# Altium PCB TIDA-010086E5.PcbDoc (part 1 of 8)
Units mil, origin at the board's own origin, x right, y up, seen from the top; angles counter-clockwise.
Board outline 6400 x 6200 mil, 6 copper layers (Top Layer, Power, AGND, Signal, PGND, Bottom Layer), stack 70.536 mil thick; 717 components, 376 nets, 2259 pads, 2183 vias.
Unrouted connection lines stored in the file: 1424.
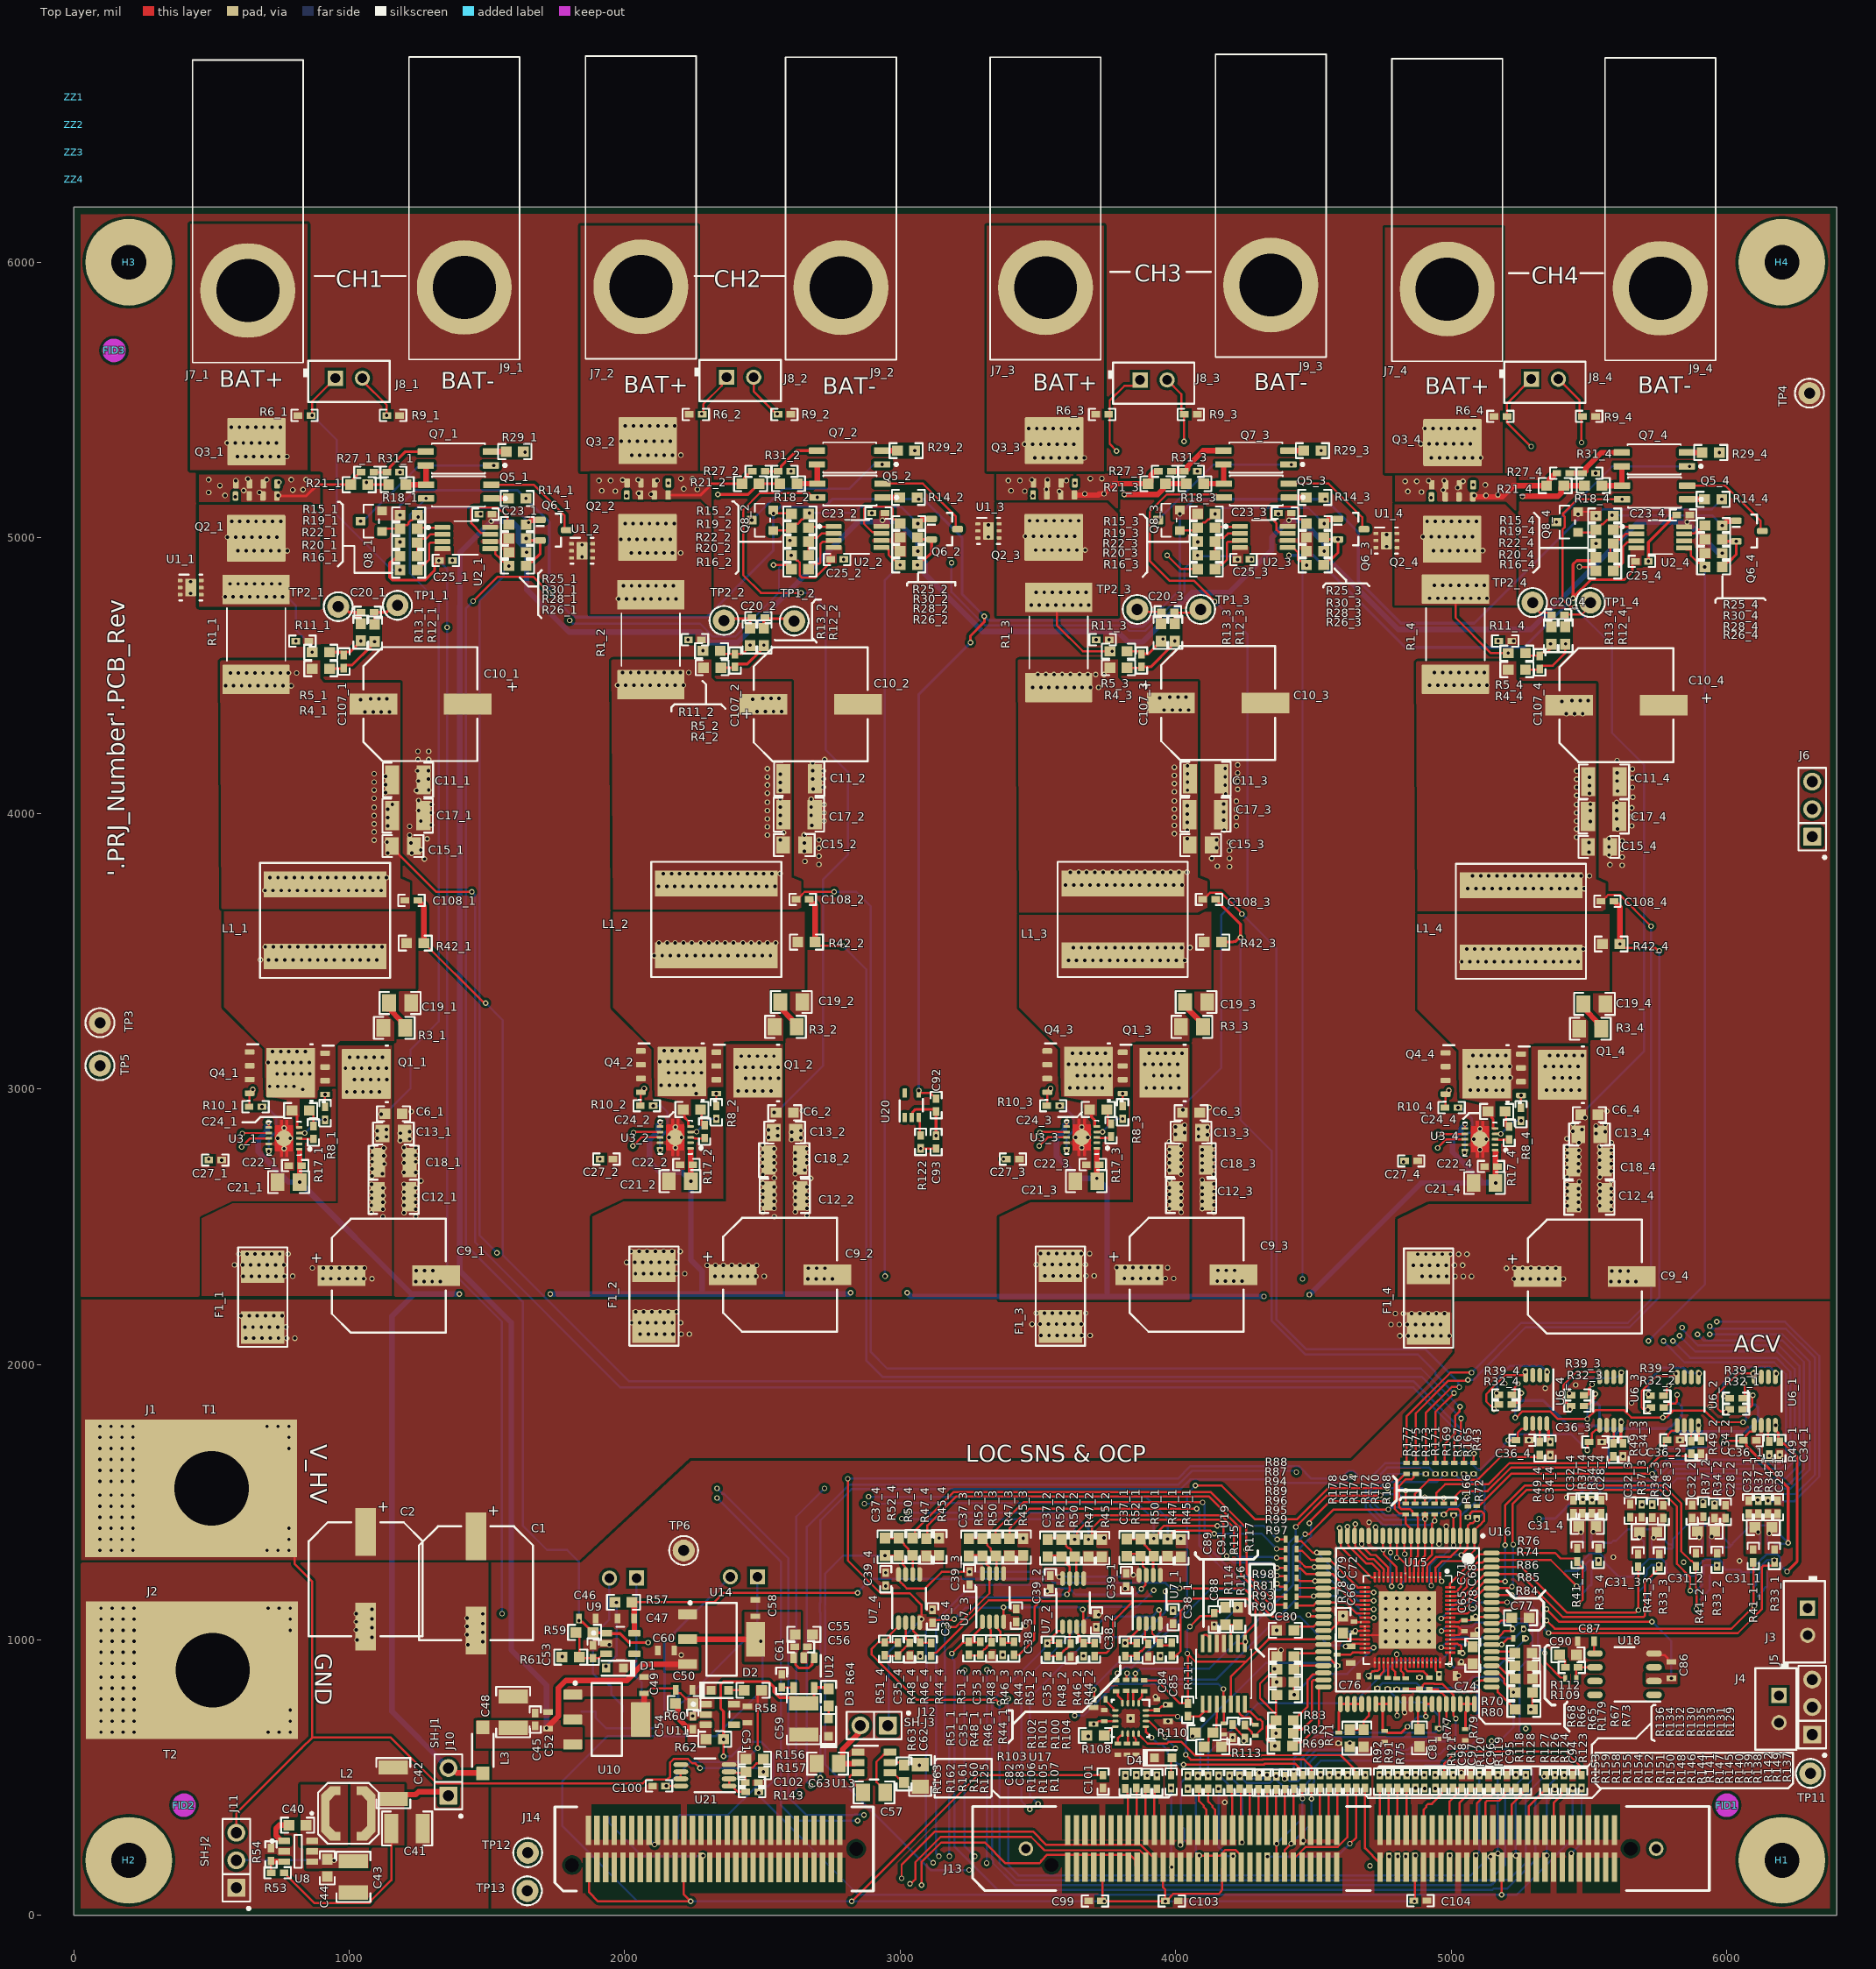
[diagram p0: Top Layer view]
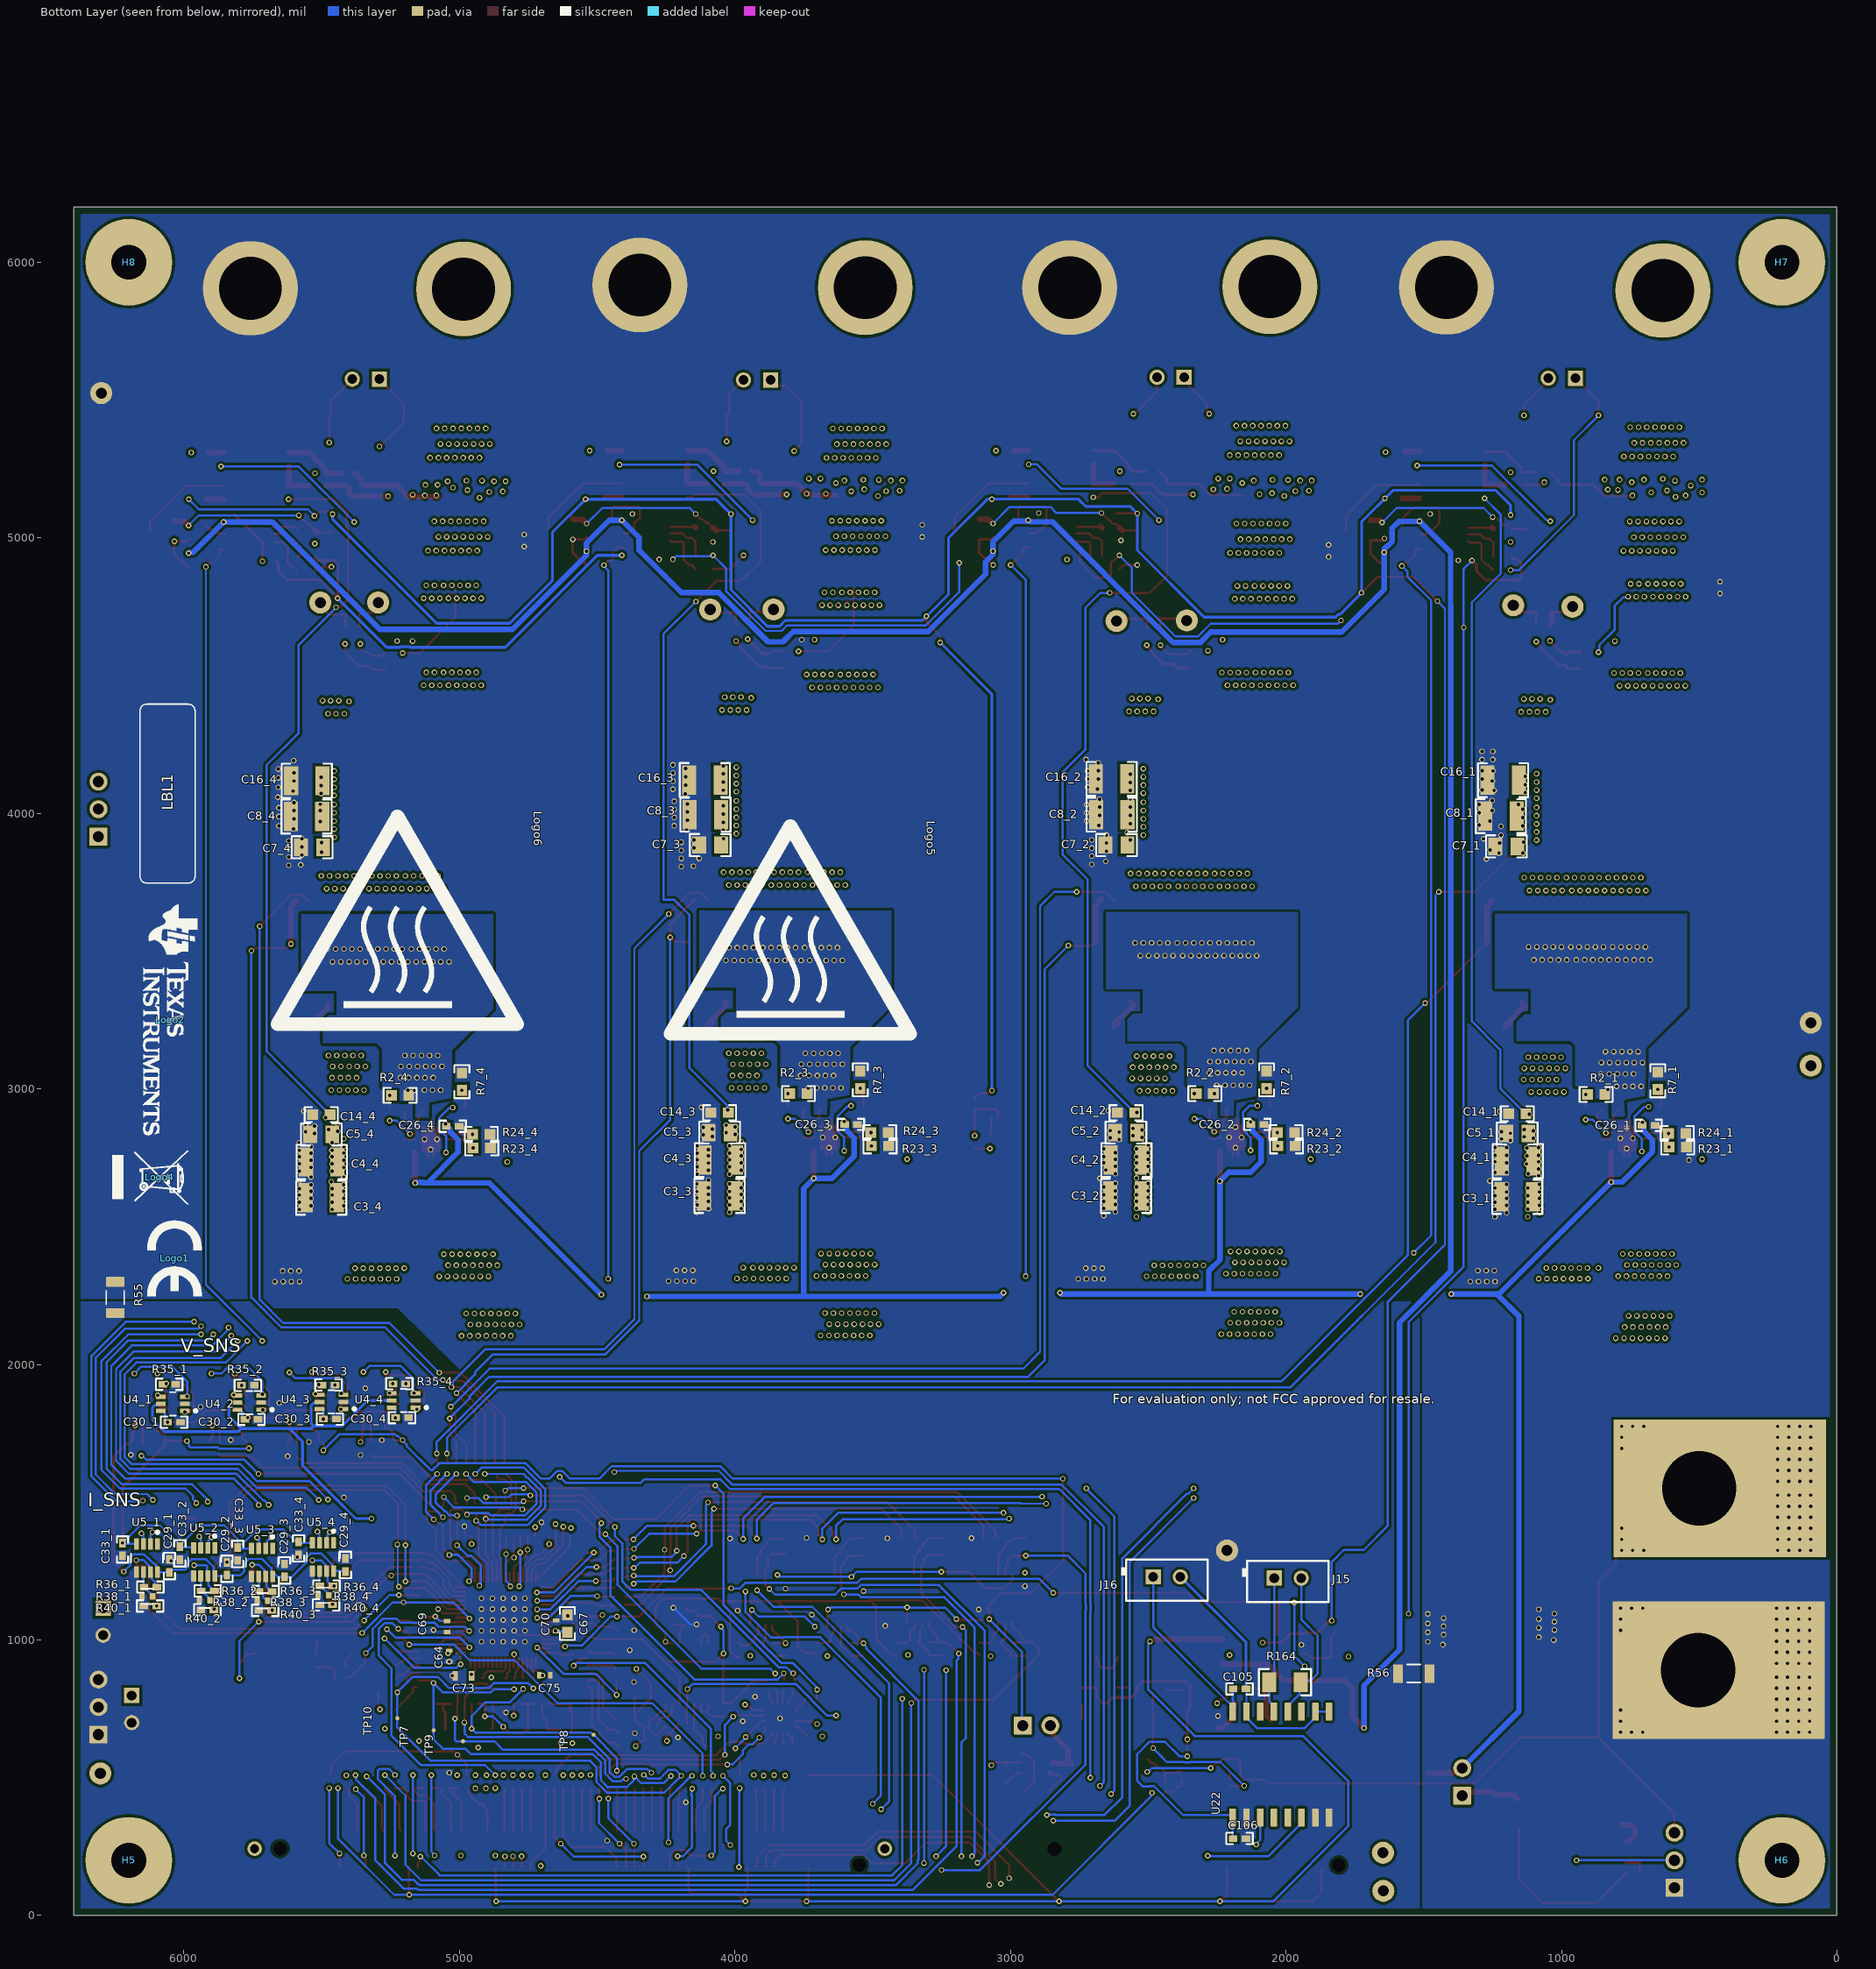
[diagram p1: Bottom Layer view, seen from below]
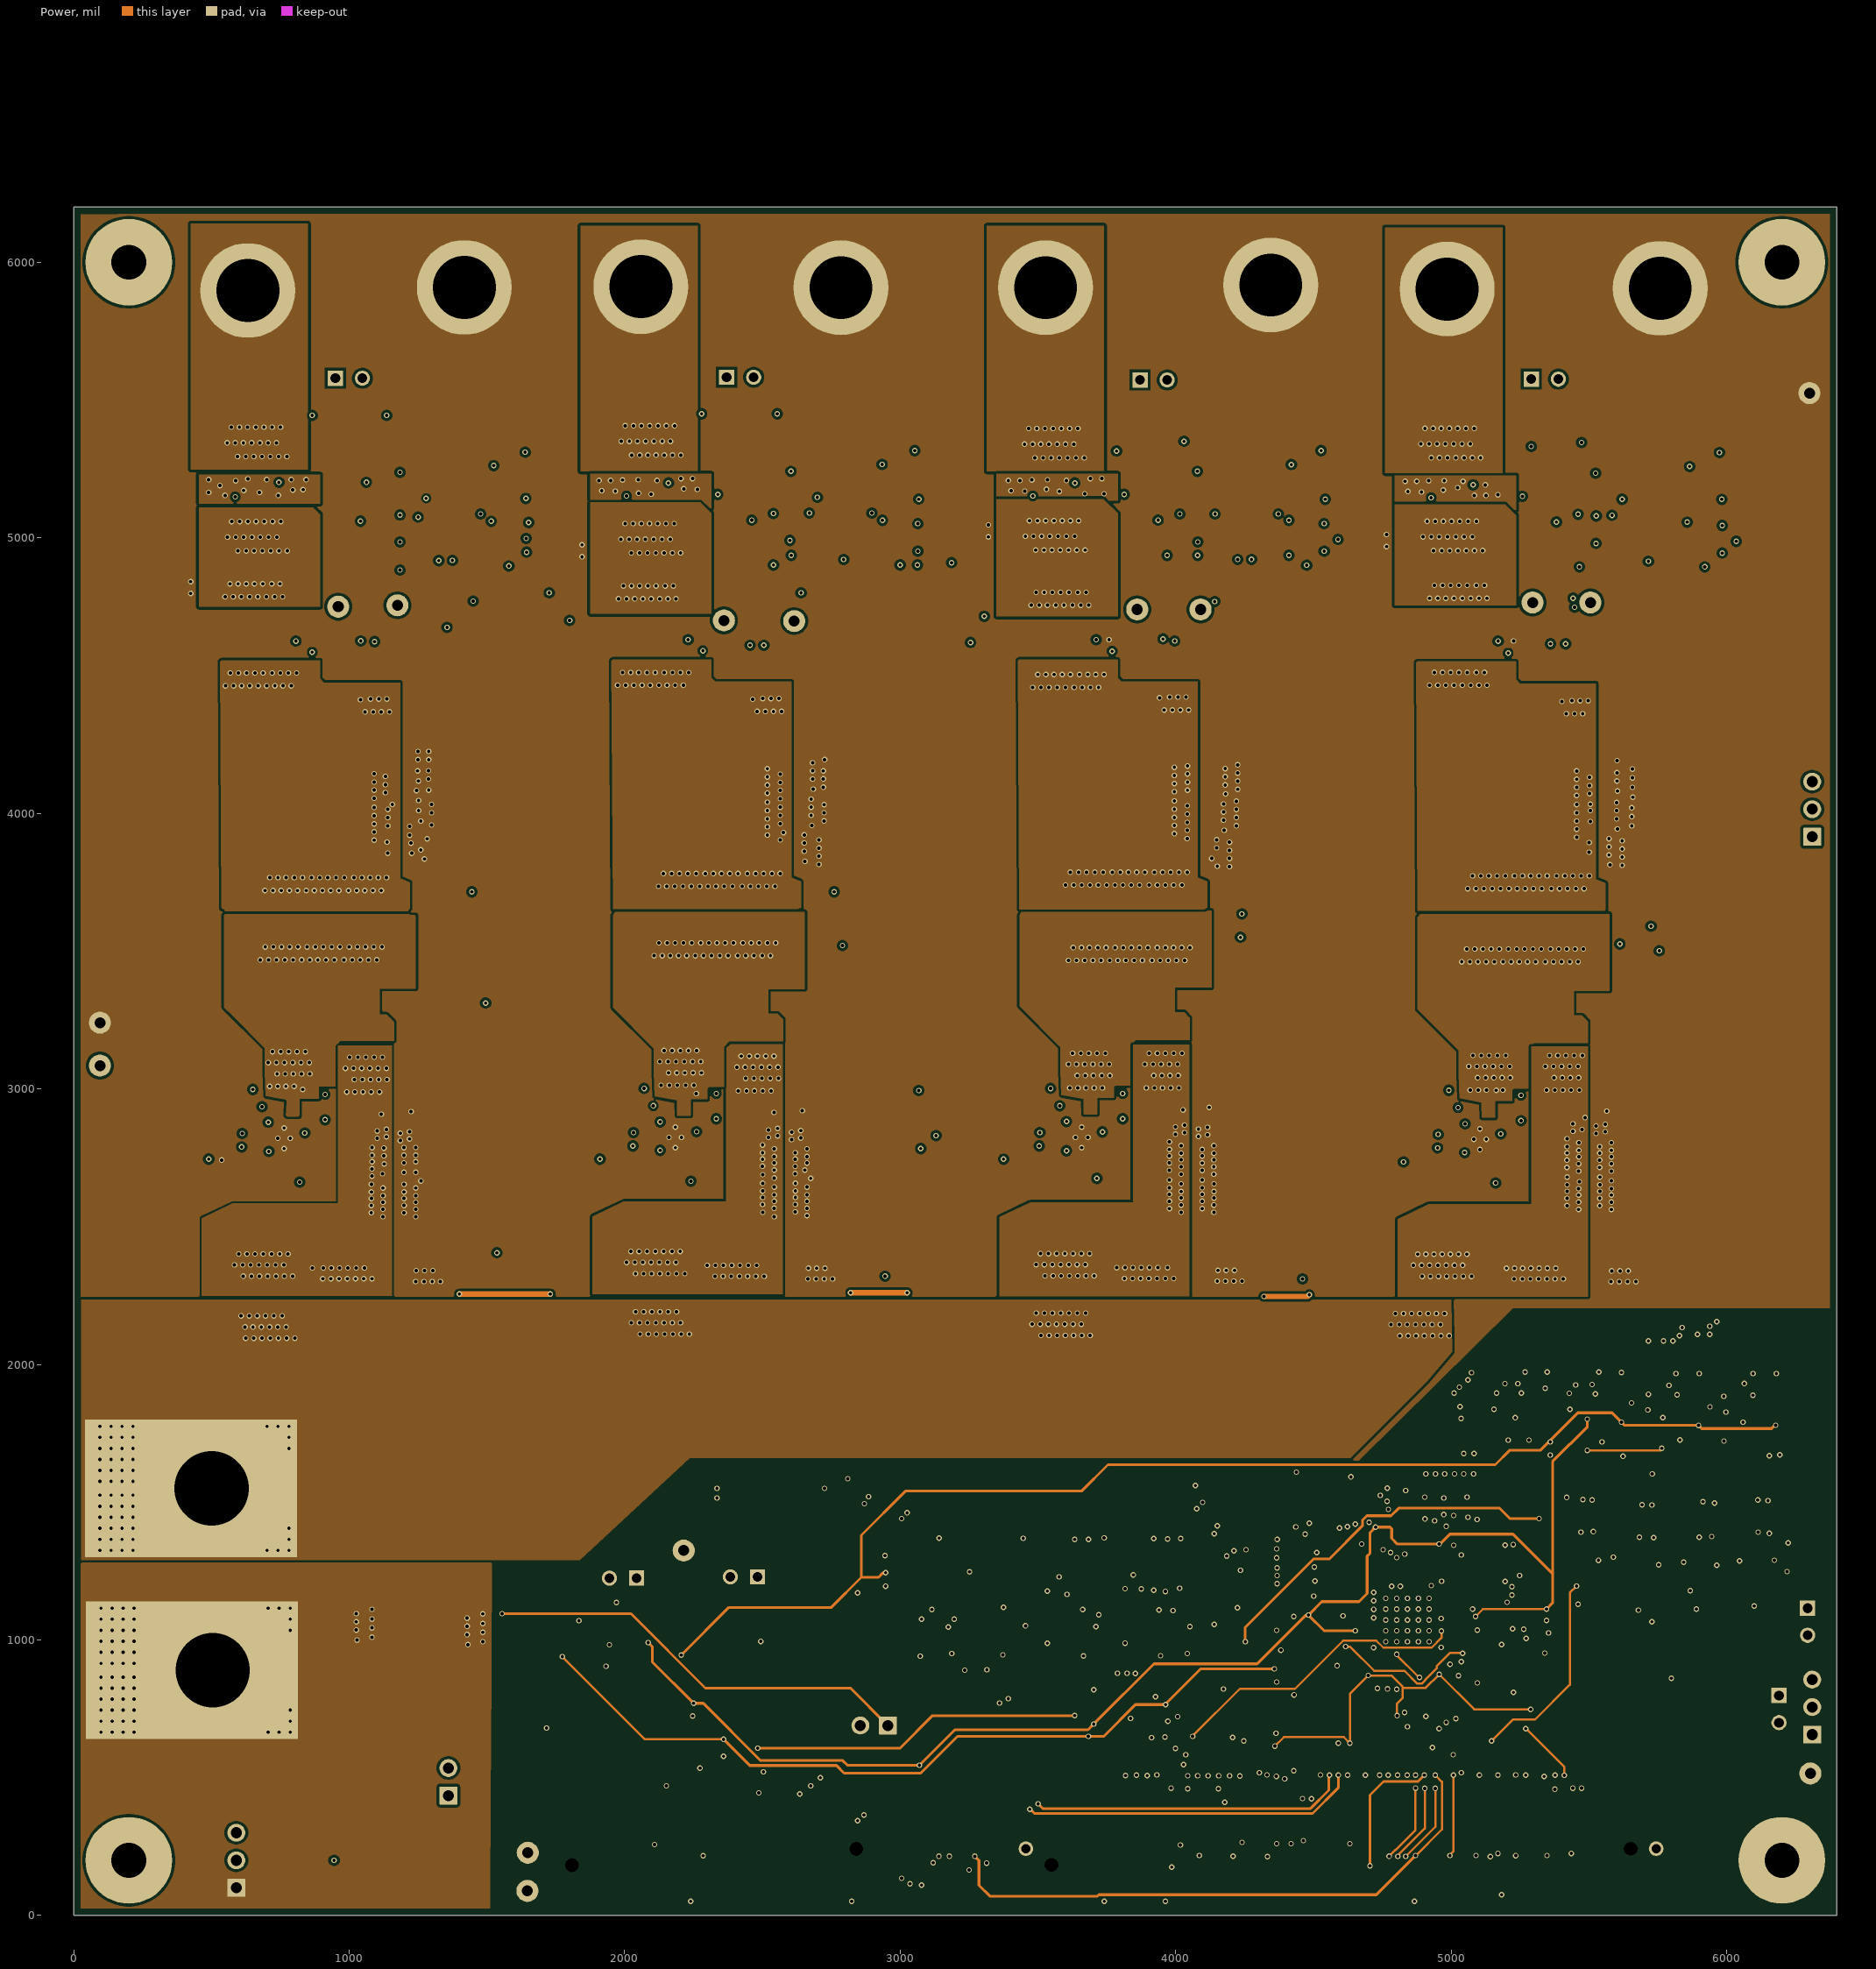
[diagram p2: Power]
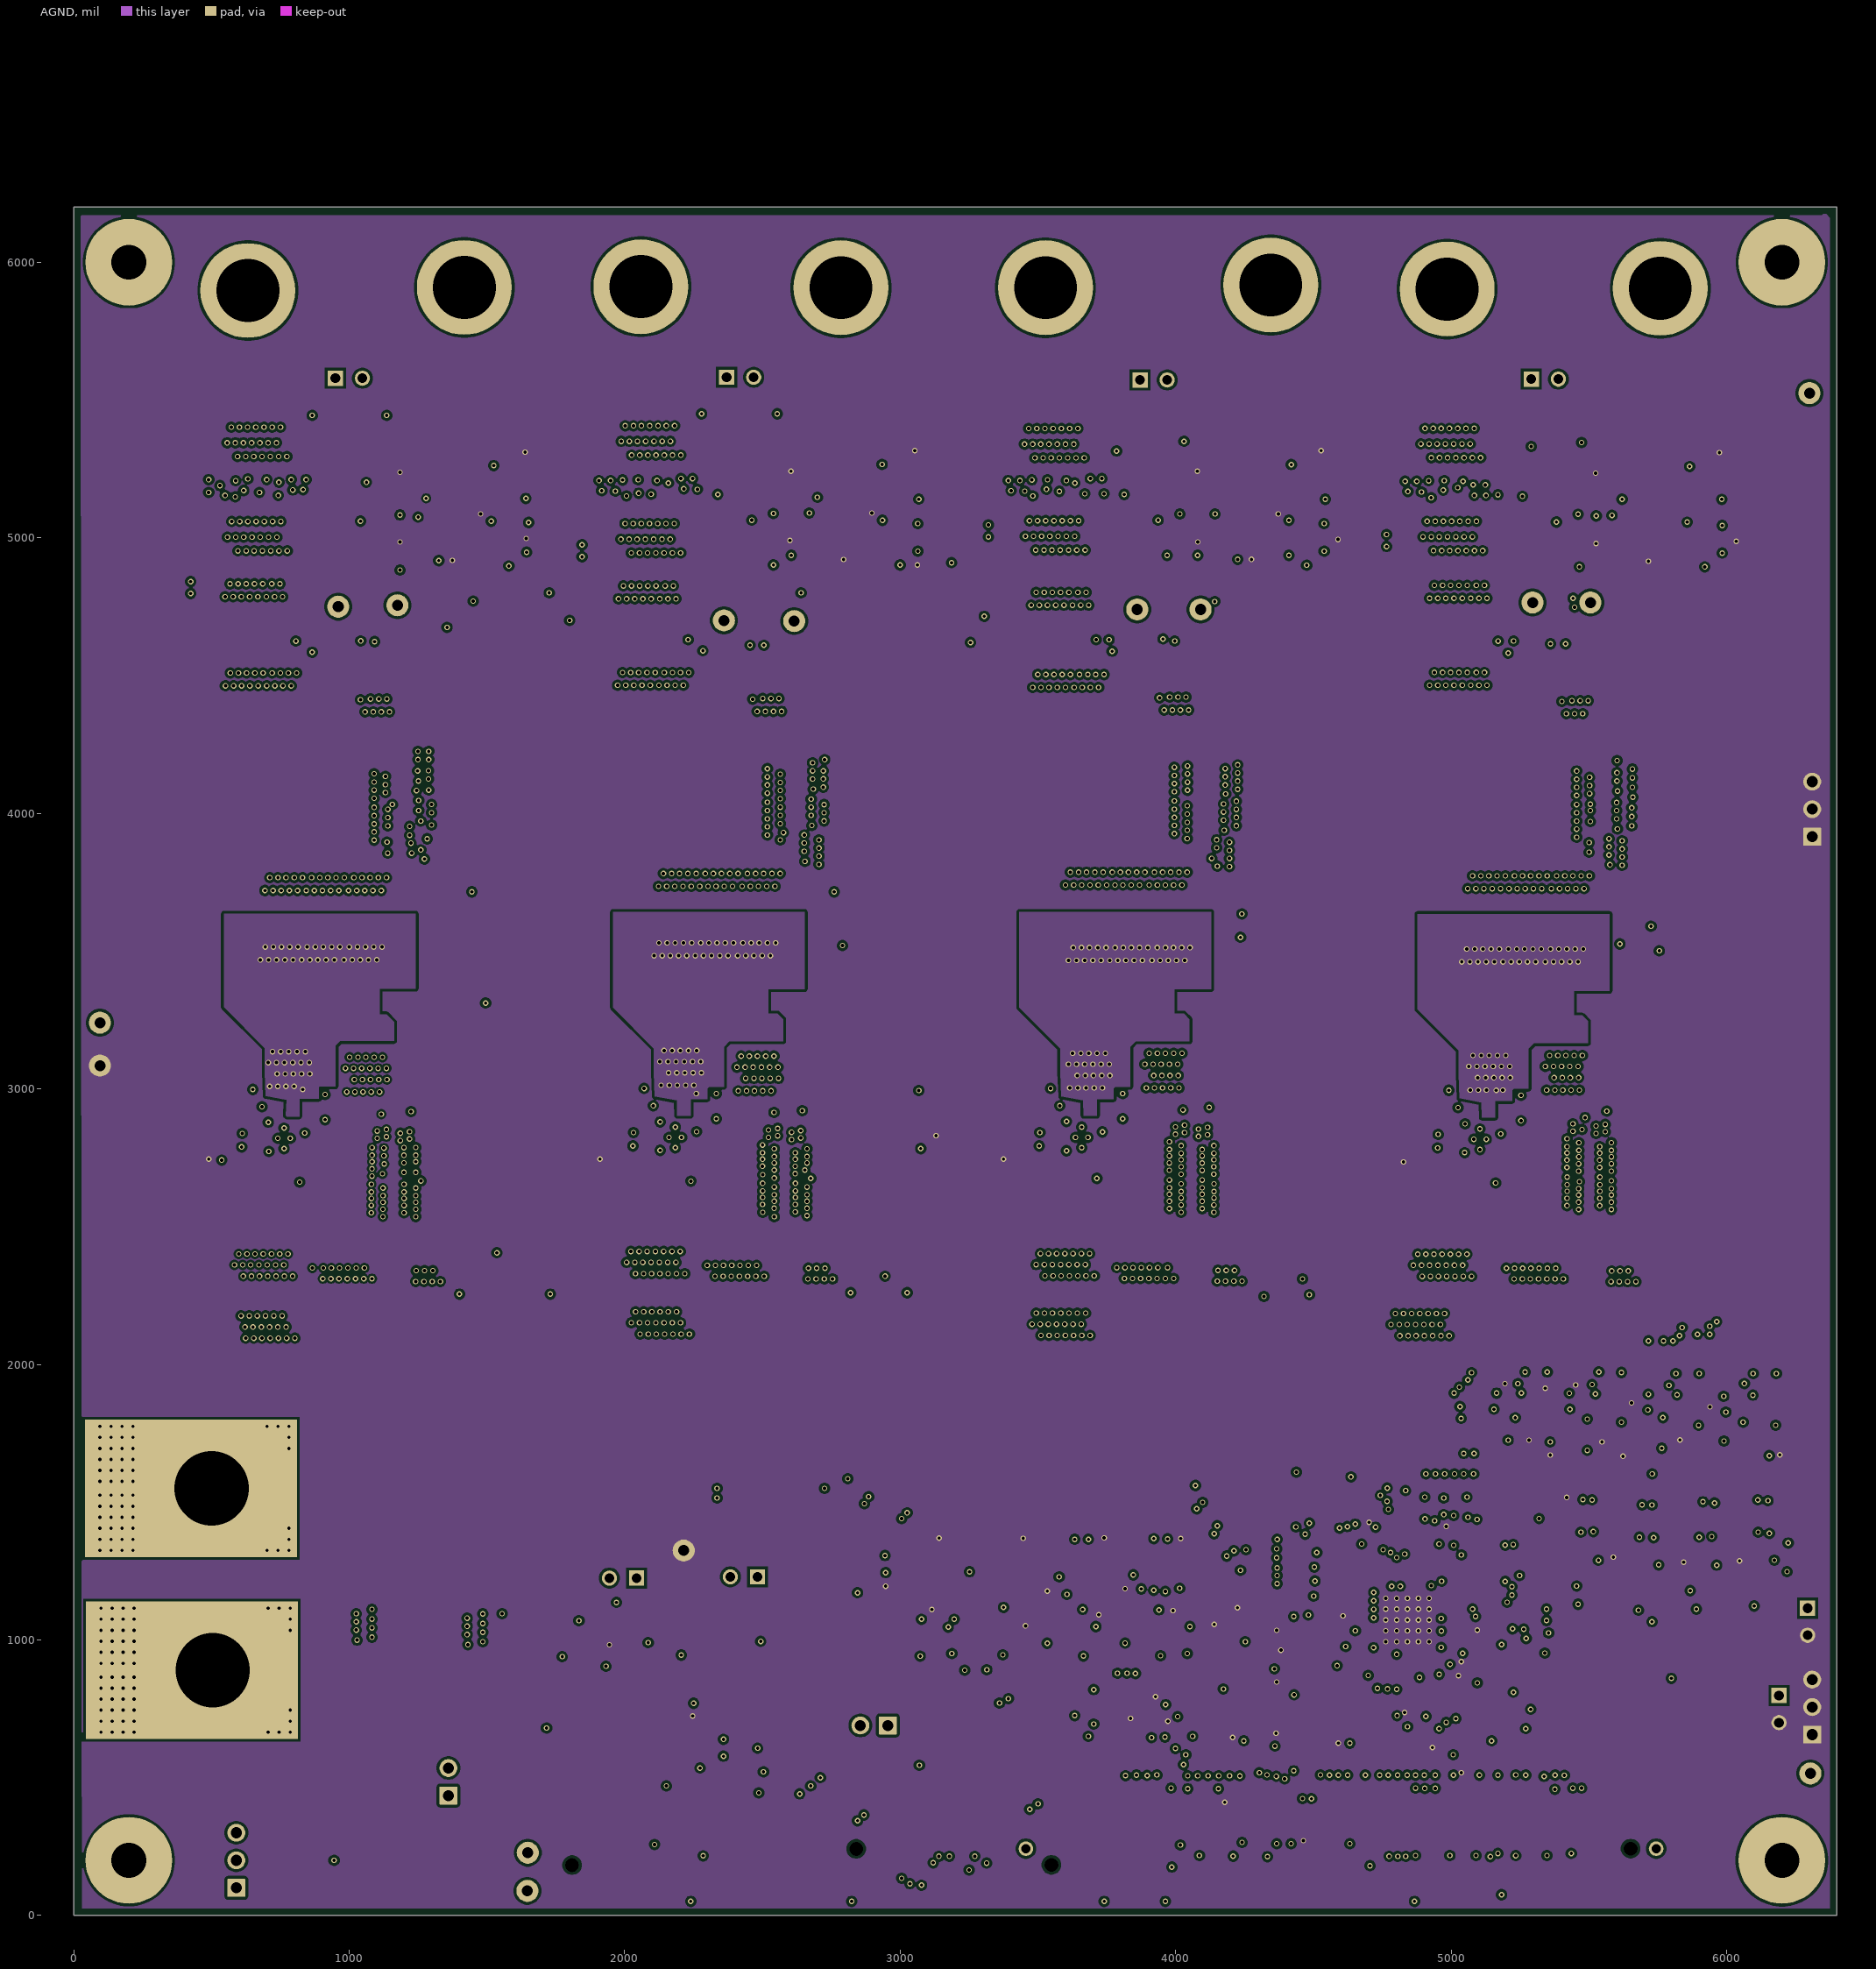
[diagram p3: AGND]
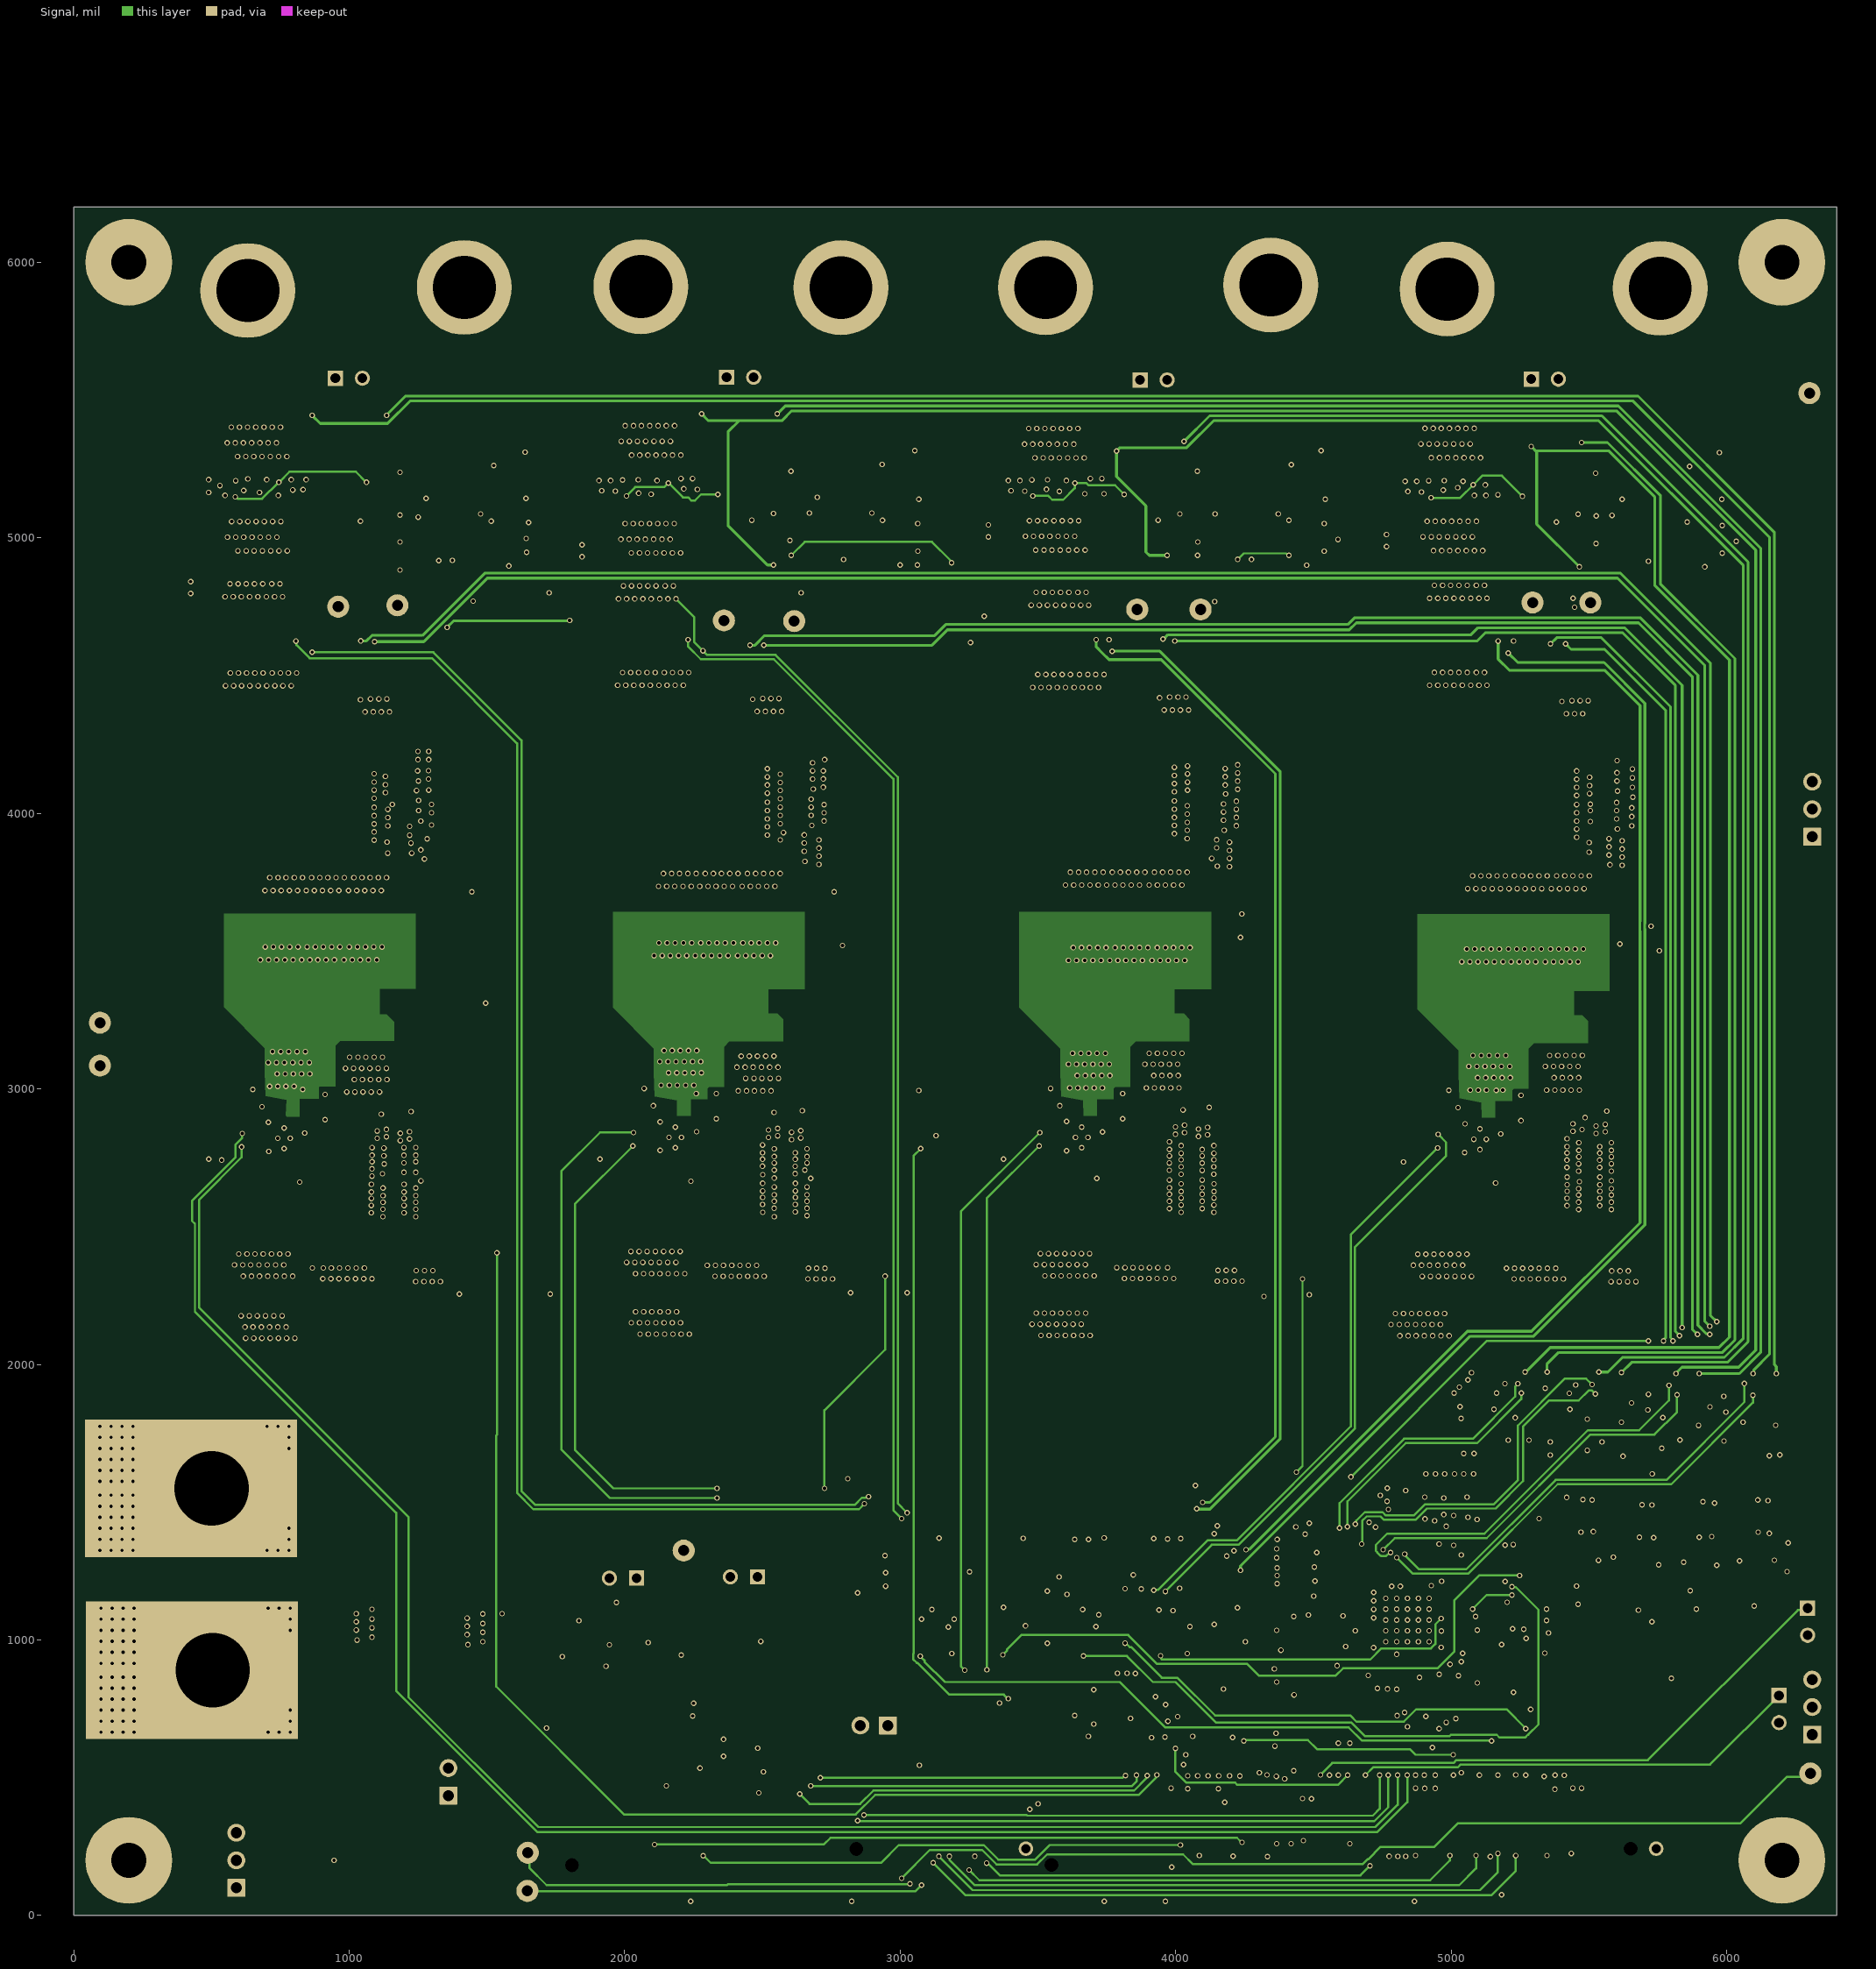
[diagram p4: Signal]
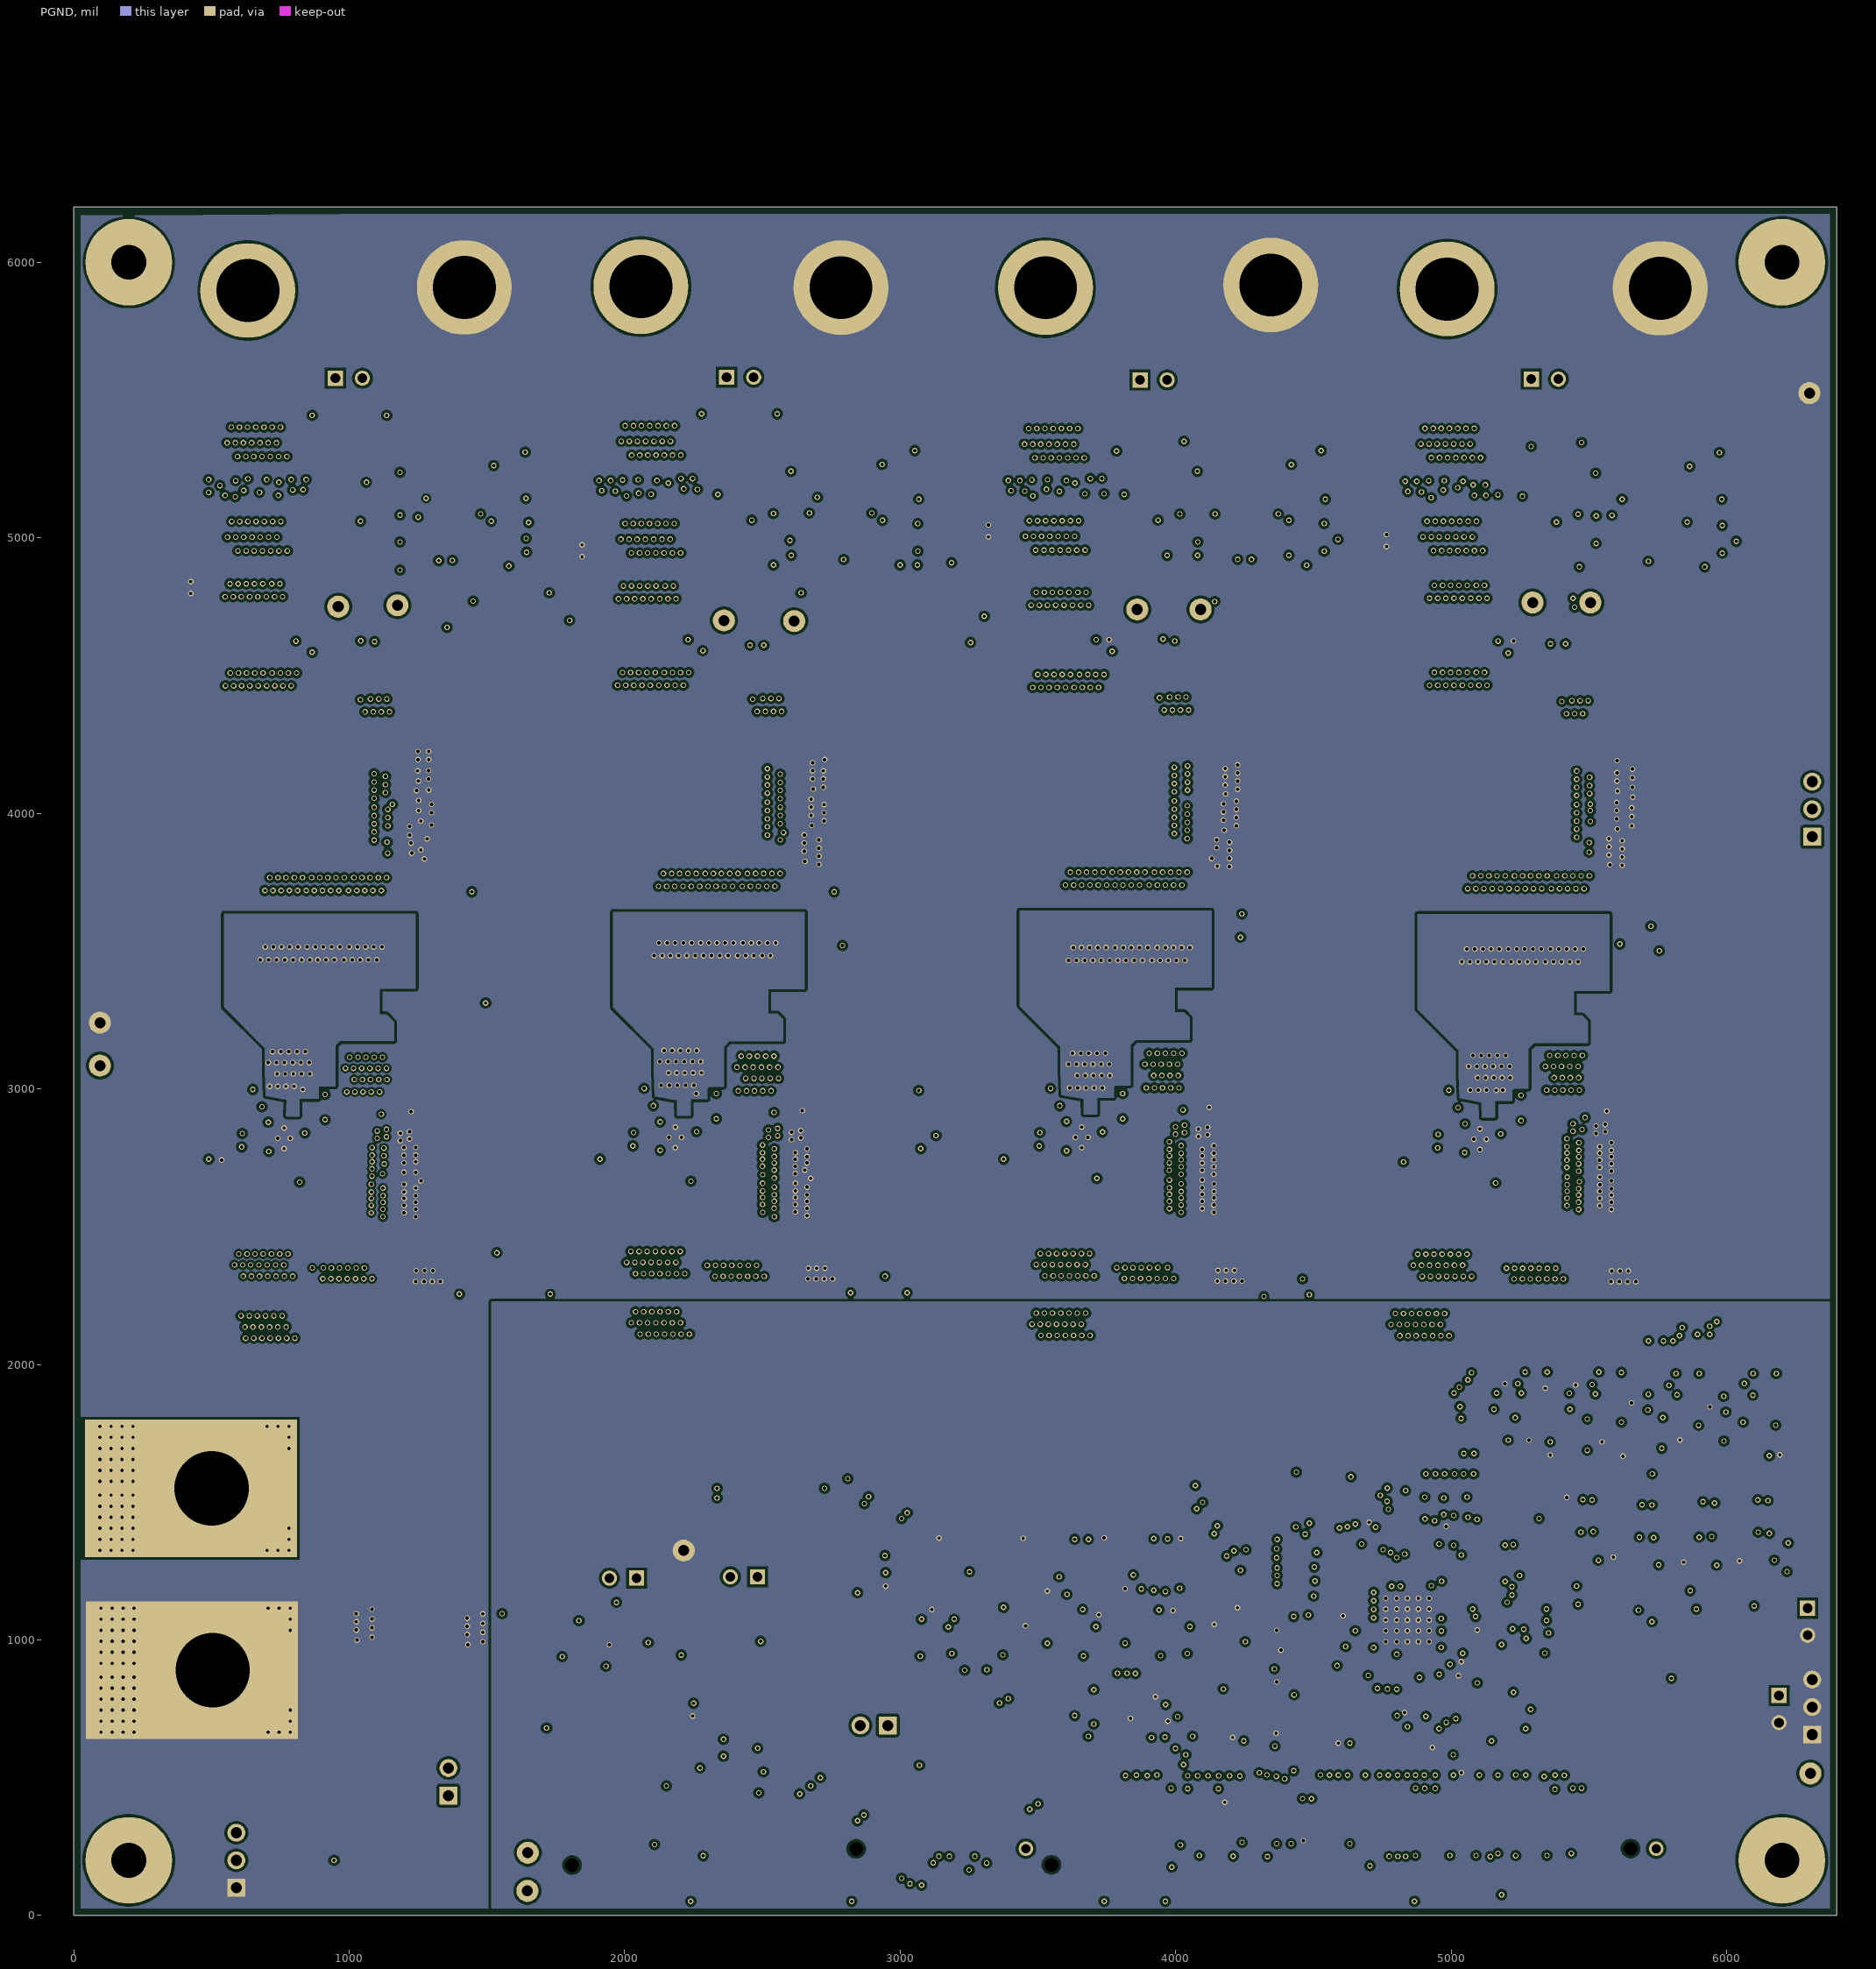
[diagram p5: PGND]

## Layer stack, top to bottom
Top Solder: solder mask 1, SM-001, Dk 4
Top Layer: signal copper 2.756
Dielectric 6: prepreg 2.8, PP-006, Dk 4.1
Dielectric 1: prepreg 5.1, PP-017, Dk 4.3
Power: signal copper 2.7559
Dielectric 4: prepreg 5.1, PP-017, Dk 4.3
AGND: signal copper 2.756
Dielectric 2: core 28, Core-039, Dk 4.8
Signal: signal copper 2.756
Dielectric 5: prepreg 5.1, PP-017, Dk 4.3
PGND: signal copper 2.7559
Dielectric 3: prepreg 5.1, PP-017, Dk 4.3
Dielectric 7: prepreg 2.8, PP-006, Dk 4.1
Bottom Layer: signal copper 2.756
Bottom Solder: solder mask 1, SM-001, Dk 4

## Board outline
0,0 6400,0 6400,6200 0,6200

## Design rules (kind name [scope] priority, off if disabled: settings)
AcuteAngle [All] p1: minimum=4.50000000000000E+0001 checktracksonly=FALSE
AssemblyTestPointUsage [All] p1: valid=2
BoardOutlineClearance BoardOutlineClearance_MountingHoles [OnCopper and InComponentClass('Mounting Holes')] p1: gap=39.37 ignorepadtopadclearanceinfootprint=FALSE
BoardOutlineClearance BoardOutlineClearance_Poly [OnCopper and IsPoly] p2: gap=25 ignorepadtopadclearanceinfootprint=FALSE
BoardOutlineClearance [OnCopper and Not InComponentClass('Logo') and not InComponentClass('FiducialMark') and not InRegion(1000,500,4000,800) and not InPoly] p3: gap=40 ignorepadtopadclearanceinfootprint=FALSE
Clearance Clearance_1 [InNet('VIN_1')] p1: gap=7.87 ignorepadtopadclearanceinfootprint=TRUE except(0: Arc-Hole Track-Hole SMDPad-Hole THPad-Hole Via-Hole Fill-Hole Poly-Hole Region-Hole Text-Hole)
Clearance Clearance_Keepouts [((IsTrack Or IsArc) And Not InPoly) And IsFree and IsKeepOut vs ((IsTrack Or IsArc) And Not InPoly) And IsFree and IsKeepOut] p2: gap=0 ignorepadtopadclearanceinfootprint=FALSE
Clearance Clearance_Poly [InPolygon] p3: gap=10 ignorepadtopadclearanceinfootprint=TRUE
Clearance Clearance_FiducialMark [IsKeepOut and InComponentClass('FiducialMark') vs IsPad and InComponentClass('FiducialMark')] p4: gap=0 ignorepadtopadclearanceinfootprint=FALSE
Clearance [All] p5: gap=7.87 ignorepadtopadclearanceinfootprint=TRUE
ComponentClearance "ADC resistors" [InComponentClass('U_TIDA-010086E5_ADC')] p1: gap=0 collisioncheckmode=3 verticalgap=0 showdistances=FALSE
ComponentClearance screw [InComponentClass('TIDA-010086E5_TopLevel')] p2: gap=0 collisioncheckmode=3 verticalgap=0 showdistances=FALSE
ComponentClearance ComponentClearance_ADC [InComponent('U16') vs InComponent('U15')] p3: gap=0 collisioncheckmode=3 verticalgap=0 showdistances=FALSE // For ADC overlaping
ComponentClearance ComponentClearance_MountingHoles_FiducialMarks [InComponentClass('Mounting Holes') vs InComponentClass('FiducialMark')] p4: gap=50 collisioncheckmode=3 verticalgap=10 showdistances=FALSE
ComponentClearance ComponentClearance_Shunt [InComponentClass('Header') vs InComponentClass('Shunt')] p5: gap=0 collisioncheckmode=3 verticalgap=0 showdistances=FALSE
ComponentClearance ComponentClearance_Logo [InComponentClass('Logo')] p6: gap=30 collisioncheckmode=3 verticalgap=10 showdistances=FALSE
ComponentClearance ComponentClearance_ScrewToNut [(HasFootprint('NY PMS 440 0025 PH')) vs (HasFootprint('Keystone_1902C'))] p7: gap=5 collisioncheckmode=3 verticalgap=10 showdistances=FALSE
ComponentClearance ComponentClearance_MountingHoles [InComponentClass('Mounting Holes')] p8: gap=100 collisioncheckmode=3 verticalgap=100000 showdistances=FALSE
ComponentClearance ComponentClearance_SmallPassives [HasFootprint('0201*') or HasFootprint('0402*') or HasFootprint('0508') or HasFootprint('0603*') or HasFootprint('0612') or HasFootprint('0805*') or HasFootprint('0815*') or HasFootprint('0830*') or HasFootprint('1206*') or HasFootprint('1210*') or HasFootprint('1808*') or HasFootprint('1812*') or HasFootprint('1825*') or HasFootprint('2010*') or HasFootprint('2220*') or HasFootprint('2225*') or HasFootprint('2512*') or HasFootprint('2728*') or HasFootprint('3518*') vs HasFootprint('0201*') or HasFootprint('0402*') or HasFootprint('0508') or HasFootprint('0603*') or HasFootprint('0612') or HasFootprint('0805*') or HasFootprint('0815*') or HasFootprint('0830*') or HasFootprint('1206*') or HasFootprint('1210*') or HasFootprint('1808*') or HasFootprint('1812*') or HasFootprint('1825*') or HasFootprint('2010*') or HasFootprint('2220*') or HasFootprint('2225*') or HasFootprint('2512*') or HasFootprint('2728*') or HasFootprint('3518*')] p9: gap=8 collisioncheckmode=3 verticalgap=10 showdistances=FALSE
ComponentClearance ComponentClearance_THtoSMT [IsThruComponent vs IsSMTComponent] p10: gap=25 collisioncheckmode=3 verticalgap=0 showdistances=FALSE
ComponentClearance ComponentClearance_THtoTH [IsThruComponent vs IsThruComponent] p11: gap=20 collisioncheckmode=3 verticalgap=30 showdistances=FALSE
ComponentClearance [All] p12: gap=10 collisioncheckmode=3 verticalgap=10 showdistances=FALSE
DiffPairsRouting [All] p1: maxlimit=100 minlimit=10 mostfreqgap=10 toplayer_minwidth=15 toplayer_maxwidth=15 toplayer_prefwidth=15 midlayer1_minwidth=15 midlayer1_maxwidth=15 midlayer1_prefwidth=15 midlayer2_minwidth=15 midlayer2_maxwidth=15 midlayer2_prefwidth=15 midlayer3_minwidth=15 midlayer3_maxwidth=15 midlayer3_prefwidth=15 midlayer4_minwidth=15 midlayer4_maxwidth=15 midlayer4_prefwidth=15 bottomlayer_minwidth=15 bottomlayer_maxwidth=15 bottomlayer_prefwidth=15 maxuncoupledlength=1000
FabricationTestPointUsage TestPointUsage [All] p1: valid=2 allowmultiple=FALSE
FabricationTestpoint Testpoint [All] p1: side=3 testpointundercomponent=TRUE minsize=40 maxsize=100 preferedsize=60 minholesize=0 maxholesize=40 preferedholesize=32 testpointgrid=1 allowsidetop=TRUE allowsidebottom=TRUE usegrid=TRUE gridtolerance=0.01
FanoutControl Fanout_LCC [IsLCC] p1: bgadir=Out bgaviamode=Centered fanoutstyle=Auto fanoutdirection=Alternating viagrid=1 // Fanout_LCC (Default Rule)
FanoutControl Fanout_BGA [IsBGA] p2: bgadir=Out bgaviamode=Centered fanoutstyle=Auto fanoutdirection=Alternating viagrid=1 // Fanout_BGA (Default Rule)
HoleSize [All] p1: absolutevalues=TRUE maxlimit=251 minlimit=7.87 maxpercent=80.000 minpercent=20.000
MinimumAnnularRing MinimumAnnularRing_ThermalPadVias [IsVia and InAnyComponent] p1: minimumring=0
MinimumAnnularRing [All] p2: minimumring=0
MinimumSolderMaskSliver MinimumSolderMaskSliver_Logo [InComponentClass('Logo') vs InComponentClass('Logo')] p1: minsoldermaskwidth=0.7
MinimumSolderMaskSliver [All] p2: minsoldermaskwidth=0
PlaneConnect [All] p1: planeconnectstyle=Relief reliefexpansion=10 reliefentries=4 reliefconductorwidth=10 reliefairgap=10
PolygonConnect [All] p1: connectstyle=Direct reliefconductorwidth=10 reliefentries=4 polygonreliefangle="90 Angle" airgapwidth=10
RoutingVias ThermalPadVias [IsVia and InAnyComponent] p1: holewidth=7.87 width=19.68 viastyle="Through Hole" minholewidth=7.87 minwidth=19.68 maxholewidth=12.99 maxwidth=23.62
RoutingVias [All] p2: holewidth=12 width=22 viastyle="Through Hole" minholewidth=7.87 minwidth=20 maxholewidth=12.5 maxwidth=22
SilkToSilkClearance SilkToSilkClearance_Pb-FreeLogo [(HasFootprint('Pb-Free_Overlay_Medium') OR HasFootprint('Pb-Free_Overlay_Small')) vs (HasFootprint('Pb-Free_Overlay_Medium') OR HasFootprint('Pb-Free_Overlay_Small'))] p1: silktosilkclearance=0
SilkToSilkClearance [All] p2: silktosilkclearance=0
SilkToSolderMaskClearance SilkToComponentPadClearance [(IsPad or IsFill or IsRegion) and InAnycomponent] p1: minsilkscreentomaskgap=0 clearancetoexposedcopper=TRUE
SilkToSolderMaskClearance "Silk to Solder Mask Opening" [All] p2: minsilkscreentomaskgap=0 clearancetoexposedcopper=FALSE
SolderMaskExpansion [All] p1: expansion=1.97 istentingtop=FALSE
UnRoutedNet [All] p1: checkbadconnections=TRUE
ViasUnderSMD [All] p1: allowed=TRUE
Width [All] p1: maxlimit=100 minlimit=7.87 preferedwidth=10 toplayer_maxwidth=20 midlayer1_maxwidth=20 midlayer2_maxwidth=20 bottomlayer_maxwidth=20 minimp=50.000000 maximp=50.000000 favimp=50.000000 checkconnectedcopper=TRUE
17 further rules are at their usual default settings.

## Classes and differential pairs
net class ILP[1..4]: ILP1 ILP2 ILP3 ILP4
net class ILN[1..4]: ILN1 ILN2 ILN3 ILN4
channel class TIDA-010086E5_V_I_Sense: Sns1 Sns2 Sns3 Sns4
channel class TIDA-010086E5_PowerStage: 1 2 3 4
net class VoutP[1..4]: VoutP1 VoutP2 VoutP3 VoutP4
net class VbatP[1..4]: VbatP1 VbatP2 VbatP3 VbatP4
net class VbatN[1..4]: VbatN1 VbatN2 VbatN3 VbatN4
net class Vbat_ACP[1..4]: Vbat_ACP1 Vbat_ACP2 Vbat_ACP3 Vbat_ACP4
net class PWM_LO[1..4]: PWM_LO1 PWM_LO2 PWM_LO3 PWM_LO4
net class PWM_HO[1..4]: PWM_HO1 PWM_HO2 PWM_HO3 PWM_HO4
net class LOCSEN_P[1..4]: LOCSEN_P1 LOCSEN_P2 LOCSEN_P3 LOCSEN_P4
net class LOCSEN_N[1..4]: LOCSEN_N1 LOCSEN_N2 LOCSEN_N3 LOCSEN_N4
net class IoutP[1..4]: IoutP1 IoutP2 IoutP3 IoutP4
net class IoutN[1..4]: IoutN1 IoutN2 IoutN3 IoutN4
net class IOCP[1..4]: IOCP1 IOCP2 IOCP3 IOCP4
net class EN_RLY[1..4]: EN_RLY1 EN_RLY2 EN_RLY3 EN_RLY4
component class U_TIDA-010086E5_ADC: C64 C65 C66 C67 C68 C69 C70 C71 C72 C73 C74 C75 C76 C77 C78 C79 C80 C81 C82 C83 C84 C85 C86 C87 C88 C89 C90 C91 R43 R65 R66 R67 R68 R69 R70 R71 R72 R73 R74 R75 R76 R77 R78 R79 R80 R81 R82 R83 R84 R85 R86 R87 R88 R89 R90 R91 R92 R93 R94 R95 R96 R97 R98 R99 R100 R101 R102 R103 R104 R105 R106 R107 R108 R109 R110 R111 R112 R113 R114 R115 R116 R117 R165 R166 R167 R168 R169 R170 R171 R172 R173 R174 R175 R176 R177 R178 R179 TP7 TP8 TP9 TP10 U15 U16 U17 U18 U19
component class U_INDSYS2081E1_BiasPower: C40 C41 C42 C43 C44 C45 C46 C47 C48 C49 C50 C51 C52 C53 C54 C55 C56 C57 C58 C59 C60 C61 C62 C63 D1 D2 D3 J10 J11 J12 L2 L3 R53 R54 R55 R56 R57 R58 R59 R60 R61 R62 R63 R64 SH-J1 SH-J2 SH-J3 TP3 TP4 TP5 TP6 U8 U9 U10 U11 U12 U13 U14
component class TIDA-010086E5_TopLevel: C1 C2 J1 J2 J3 J4 J5 J6 J15 J16 T1 T2
component class Sns4: C28_4 C29_4 C30_4 C31_4 C32_4 C33_4 C34_4 C35_4 C36_4 C37_4 C38_4 C39_4 R32_4 R33_4 R34_4 R35_4 R36_4 R37_4 R38_4 R39_4 R40_4 R41_4 R44_4 R45_4 R46_4 R47_4 R48_4 R49_4 R50_4 R51_4 R52_4 U4_4 U5_4 U6_4 U7_4
component class Sns3: C28_3 C29_3 C30_3 C31_3 C32_3 C33_3 C34_3 C35_3 C36_3 C37_3 C38_3 C39_3 R32_3 R33_3 R34_3 R35_3 R36_3 R37_3 R38_3 R39_3 R40_3 R41_3 R44_3 R45_3 R46_3 R47_3 R48_3 R49_3 R50_3 R51_3 R52_3 U4_3 U5_3 U6_3 U7_3
component class Sns2: C28_2 C29_2 C30_2 C31_2 C32_2 C33_2 C34_2 C35_2 C36_2 C37_2 C38_2 C39_2 R32_2 R33_2 R34_2 R35_2 R36_2 R37_2 R38_2 R39_2 R40_2 R41_2 R44_2 R45_2 R46_2 R47_2 R48_2 R49_2 R50_2 R51_2 R52_2 U4_2 U5_2 U6_2 U7_2
component class Sns1: C28_1 C29_1 C30_1 C31_1 C32_1 C33_1 C34_1 C35_1 C36_1 C37_1 C38_1 C39_1 R32_1 R33_1 R34_1 R35_1 R36_1 R37_1 R38_1 R39_1 R40_1 R41_1 R44_1 R45_1 R46_1 R47_1 R48_1 R49_1 R50_1 R51_1 R52_1 U4_1 U5_1 U6_1 U7_1
component class Shunt: SH-J1 SH-J2 SH-J3
component class Header: J5 J6 J10 J11 J12
component class ControlCard: C92 C93 C94 C95 C96 C97 C98 C99 C100 C101 C102 C103 C104 C105 C106 D4 J13 J14 R118 R119 R120 R121 R122 R123 R124 R125 R126 R127 R128 R129 R130 R131 R132 R133 R134 R135 R136 R137 R138 R139 R140 R141 R142 R143 R144 R145 R146 R147 R148 R149 R150 R151 R152 R153 R154 R155 R156 R157 R158 R159 R160 R161 R162 R163 R164 TP11 TP12 TP13 U20 U21 U22
component class 4: C3_4 C4_4 C5_4 C6_4 C7_4 C8_4 C9_4 C10_4 C11_4 C12_4 C13_4 C14_4 C15_4 C16_4 C17_4 C18_4 C19_4 C20_4 C21_4 C22_4 C23_4 C24_4 C25_4 C26_4 C27_4 C107_4 C108_4 F1_4 J7_4 J8_4 J9_4 L1_4 Q1_4 Q2_4 Q3_4 Q4_4 Q5_4 Q6_4 Q7_4 Q8_4 R1_4 R2_4 R3_4 R4_4 R5_4 R6_4 R7_4 R8_4 R9_4 R10_4 R11_4 R12_4 R13_4 R14_4 R15_4 R16_4 R17_4 R18_4 R19_4 R20_4 R21_4 R22_4 R23_4 R24_4 R25_4 R26_4 R27_4 R28_4 R29_4 R30_4 R31_4 R42_4 TP1_4 TP2_4 U1_4 U2_4 U3_4
component class 3: C3_3 C4_3 C5_3 C6_3 C7_3 C8_3 C9_3 C10_3 C11_3 C12_3 C13_3 C14_3 C15_3 C16_3 C17_3 C18_3 C19_3 C20_3 C21_3 C22_3 C23_3 C24_3 C25_3 C26_3 C27_3 C107_3 C108_3 F1_3 J7_3 J8_3 J9_3 L1_3 Q1_3 Q2_3 Q3_3 Q4_3 Q5_3 Q6_3 Q7_3 Q8_3 R1_3 R2_3 R3_3 R4_3 R5_3 R6_3 R7_3 R8_3 R9_3 R10_3 R11_3 R12_3 R13_3 R14_3 R15_3 R16_3 R17_3 R18_3 R19_3 R20_3 R21_3 R22_3 R23_3 R24_3 R25_3 R26_3 R27_3 R28_3 R29_3 R30_3 R31_3 R42_3 TP1_3 TP2_3 U1_3 U2_3 U3_3
component class 2: C3_2 C4_2 C5_2 C6_2 C7_2 C8_2 C9_2 C10_2 C11_2 C12_2 C13_2 C14_2 C15_2 C16_2 C17_2 C18_2 C19_2 C20_2 C21_2 C22_2 C23_2 C24_2 C25_2 C26_2 C27_2 C107_2 C108_2 F1_2 J7_2 J8_2 J9_2 L1_2 Q1_2 Q2_2 Q3_2 Q4_2 Q5_2 Q6_2 Q7_2 Q8_2 R1_2 R2_2 R3_2 R4_2 R5_2 R6_2 R7_2 R8_2 R9_2 R10_2 R11_2 R12_2 R13_2 R14_2 R15_2 R16_2 R17_2 R18_2 R19_2 R20_2 R21_2 R22_2 R23_2 R24_2 R25_2 R26_2 R27_2 R28_2 R29_2 R30_2 R31_2 R42_2 TP1_2 TP2_2 U1_2 U2_2 U3_2
component class 1: C3_1 C4_1 C5_1 C6_1 C7_1 C8_1 C9_1 C10_1 C11_1 C12_1 C13_1 C14_1 C15_1 C16_1 C17_1 C18_1 C19_1 C20_1 C21_1 C22_1 C23_1 C24_1 C25_1 C26_1 C27_1 C107_1 C108_1 F1_1 J7_1 J8_1 J9_1 L1_1 Q1_1 Q2_1 Q3_1 Q4_1 Q5_1 Q6_1 Q7_1 Q8_1 R1_1 R2_1 R3_1 R4_1 R5_1 R6_1 R7_1 R8_1 R9_1 R10_1 R11_1 R12_1 R13_1 R14_1 R15_1 R16_1 R17_1 R18_1 R19_1 R20_1 R21_1 R22_1 R23_1 R24_1 R25_1 R26_1 R27_1 R28_1 R29_1 R30_1 R31_1 R42_1 TP1_1 TP2_1 U1_1 U2_1 U3_1
component class "Mounting Holes": H1 H2 H3 H4
component class Logo: Logo2
component class FiducialMark: FID1 FID2 FID3
component class AssemblyNote: ZZ1 ZZ2 ZZ3 ZZ4
component class Label: LBL1

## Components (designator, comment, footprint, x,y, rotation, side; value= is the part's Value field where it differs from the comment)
C1 "A768MS157M1HLAE024" CAPSMT_62_F12 1460,1205 r270 top value=150uF
C2 "A768MS157M1HLAE024" CAPSMT_62_F12 1060,1220 r270 top value=150uF
C3_1 "GMK325BJ226MM-P" 1210 1160.55,2607.83 r0 bottom value=22uF (schematic designator C3)
C3_2 "GMK325BJ226MM-P" 1210 2580.67,2611.42 r0 bottom value=22uF (schematic designator C3)
C3_3 "GMK325BJ226MM-P" 1210 4055.67,2611.42 r0 bottom value=22uF (schematic designator C3)
C3_4 "GMK325BJ226MM-P" 1210 5501.45,2604.58 r0 bottom value=22uF (schematic designator C3)
C4_1 "GMK325BJ226MM-P" 1210 1158.78,2737.83 r0 bottom value=22uF (schematic designator C4)
C4_2 "GMK325BJ226MM-P" 1210 2578.9,2741.42 r0 bottom value=22uF (schematic designator C4)
C4_3 "GMK325BJ226MM-P" 1210 4053.9,2741.42 r0 bottom value=22uF (schematic designator C4)
C4_4 "GMK325BJ226MM-P" 1210 5499.68,2734.58 r0 bottom value=22uF (schematic designator C4)
C5_1 "GRM21BR71H105KA12L" 0805_HV 1160.55,2837.83 r0 bottom value=1uF (schematic designator C5)
C5_2 "GRM21BR71H105KA12L" 0805_HV 2580.67,2841.42 r0 bottom value=1uF (schematic designator C5)
C5_3 "GRM21BR71H105KA12L" 0805_HV 4055.67,2841.42 r0 bottom value=1uF (schematic designator C5)
C5_4 "GRM21BR71H105KA12L" 0805_HV 5501.45,2834.58 r0 bottom value=1uF (schematic designator C5)
C6_1 "GRM188R72A104KA35D" 0603 1160.55,2909.72 r0 top value=0.1uF (schematic designator C6)
C6_2 "GRM188R72A104KA35D" 0603 2580.67,2913.31 r0 top value=0.1uF (schematic designator C6)
C6_3 "GRM188R72A104KA35D" 0603 4055.67,2913.31 r0 top value=0.1uF (schematic designator C6)
C6_4 "GRM188R72A104KA35D" 0603 5501.45,2906.47 r0 top value=0.1uF (schematic designator C6)
C7_1 "GRM21BR71H105KA12L" 0805_HV 1200,3880 r0 bottom value=1uF (schematic designator C7)
C7_2 "GRM21BR71H105KA12L" 0805_HV 2615.21,3885 r0 bottom value=1uF (schematic designator C7)
C7_3 "GRM21BR71H105KA12L" 0805_HV 4090,3885 r0 bottom value=1uF (schematic designator C7)
C7_4 "GRM21BR71H105KA12L" 0805_HV 5535,3876.84 r0 bottom value=1uF (schematic designator C7)
C8_1 "GRM32EC81C476ME15L" 1210_270 1220,3990 r0 bottom value=47uF (schematic designator C8)
C8_2 "GRM32EC81C476ME15L" 1210_270 2632.3,3995 r0 bottom value=47uF (schematic designator C8)
C8_3 "GRM32EC81C476ME15L" 1210_270 4107.3,3995 r0 bottom value=47uF (schematic designator C8)
C8_4 "GRM32EC81C476ME15L" 1210_270 5555,3988.16 r0 bottom value=47uF (schematic designator C8)
C9_1 "A768MS157M1HLAE024" CAPSMT_62_F12 1143.62,2321.42 r0 top value=150uF (schematic designator C9)
C9_2 "A768MS157M1HLAE024" CAPSMT_62_F12 2563.74,2325 r0 top value=150uF (schematic designator C9)
C9_3 "A768MS157M1HLAE024" CAPSMT_62_F12 4038.74,2325 r0 top value=150uF (schematic designator C9)
C9_4 "A768MS157M1HLAE024" CAPSMT_62_F12 5484.52,2318.16 r0 top value=150uF (schematic designator C9)
C10_1 "A768MS157M1HLAE024" CAPSMT_62_F12 1258.7,4396.42 r0 top value=150uF (schematic designator C10)
C10_2 "A768MS157M1HLAE024" CAPSMT_62_F12 2675,4395 r0 top value=150uF (schematic designator C10)
C10_3 "A768MS157M1HLAE024" CAPSMT_62_F12 4153.82,4400 r0 top value=150uF (schematic designator C10)
C10_4 "A768MS157M1HLAE024" CAPSMT_62_F12 5599.6,4393.16 r0 top value=150uF (schematic designator C10)
C11_1 "GRM32EC81C476ME15L" 1210_270 1213.08,4121.42 r0 top value=47uF (schematic designator C11)
C11_2 "GRM32EC81C476ME15L" 1210_270 2633.2,4125 r0 top value=47uF (schematic designator C11)
C11_3 "GRM32EC81C476ME15L" 1210_270 4108.2,4125 r0 top value=47uF (schematic designator C11)
C11_4 "GRM32EC81C476ME15L" 1210_270 5554.52,4115 r0 top value=47uF (schematic designator C11)
C12_1 "GMK325BJ226MM-P" 1210 1160.55,2607.83 r0 top value=22uF (schematic designator C12)
C12_2 "GMK325BJ226MM-P" 1210 2580.67,2611.42 r0 top value=22uF (schematic designator C12)
C12_3 "GMK325BJ226MM-P" 1210 4055.67,2611.42 r0 top value=22uF (schematic designator C12)
C12_4 "GMK325BJ226MM-P" 1210 5501.45,2604.58 r0 top value=22uF (schematic designator C12)
C13_1 "GRM21BR71H105KA12L" 0805_HV 1160.55,2837.83 r0 top value=1uF (schematic designator C13)
C13_2 "GRM21BR71H105KA12L" 0805_HV 2580.67,2841.42 r0 top value=1uF (schematic designator C13)
C13_3 "GRM21BR71H105KA12L" 0805_HV 4055.67,2841.42 r0 top value=1uF (schematic designator C13)
C13_4 "GRM21BR71H105KA12L" 0805_HV 5501.45,2834.58 r0 top value=1uF (schematic designator C13)
C14_1 "GRM188R72A104KA35D" 0603 1160.55,2909.72 r0 bottom value=0.1uF (schematic designator C14)
C14_2 "GRM188R72A104KA35D" 0603 2580.67,2913.31 r0 bottom value=0.1uF (schematic designator C14)
C14_3 "GRM188R72A104KA35D" 0603 4055.67,2913.31 r0 bottom value=0.1uF (schematic designator C14)
C14_4 "GRM188R72A104KA35D" 0603 5501.45,2906.47 r0 bottom value=0.1uF (schematic designator C14)
C15_1 "GRM21BR71H105KA12L" 0805_HV 1195.09,3881.42 r0 top value=1uF (schematic designator C15)
C15_2 "GRM21BR71H105KA12L" 0805_HV 2615.21,3885 r0 top value=1uF (schematic designator C15)
C15_3 "GRM21BR71H105KA12L" 0805_HV 4090.21,3885 r0 top value=1uF (schematic designator C15)
C15_4 "GRM21BR71H105KA12L" 0805_HV 5535.99,3878.16 r0 top value=1uF (schematic designator C15)
C16_1 "GRM32EC81C476ME15L" 1210_270 1212.09,4120 r0 bottom value=47uF (schematic designator C16)
C16_2 "GRM32EC81C476ME15L" 1210_270 2633.2,4125 r0 bottom value=47uF (schematic designator C16)
C16_3 "GRM32EC81C476ME15L" 1210_270 4109.3,4120.97 r0 bottom value=47uF (schematic designator C16)
C16_4 "GRM32EC81C476ME15L" 1210_270 5553.98,4118.16 r0 bottom value=47uF (schematic designator C16)
C17_1 "GRM32EC81C476ME15L" 1210_270 1212.18,3991.42 r0 top value=47uF (schematic designator C17)
C17_2 "GRM32EC81C476ME15L" 1210_270 2632.3,3995 r0 top value=47uF (schematic designator C17)
C17_3 "GRM32EC81C476ME15L" 1210_270 4107.3,3995 r0 top value=47uF (schematic designator C17)
C17_4 "GRM32EC81C476ME15L" 1210_270 5553.08,3988.16 r0 top value=47uF (schematic designator C17)
C18_1 "GMK325BJ226MM-P" 1210 1161.79,2732.15 r0 top value=22uF (schematic designator C18)
C18_2 "GMK325BJ226MM-P" 1210 2578.9,2741.42 r0 top value=22uF (schematic designator C18)
C18_3 "GMK325BJ226MM-P" 1210 4053.9,2741.42 r0 top value=22uF (schematic designator C18)
C18_4 "GMK325BJ226MM-P" 1210 5499.68,2734.58 r0 top value=22uF (schematic designator C18)
C19_1 "GRM2165C2A101JA01D" 0805_HV 1184.52,3311.42 r0 top value=100pF (schematic designator C19)
C19_2 "GRM2165C2A101JA01D" 0805_HV 2604.64,3315 r0 top value=100pF (schematic designator C19)
C19_3 "GRM2165C2A101JA01D" 0805_HV 4073.74,3315 r0 top value=100pF (schematic designator C19)
C19_4 "GRM2165C2A101JA01D" 0805_HV 5519.52,3308.16 r0 top value=100pF (schematic designator C19)
C20_1 "GRM155R71C153KA01D" 0402 1066.84,4729.47 r180 top value=0.015uF (schematic designator C20)
C20_2 "GRM155R71C153KA01D" 0402 2485,4710 r180 top value=0.015uF (schematic designator C20)
C20_3 "GRM155R71C153KA01D" 0402 3971.18,4731.65 r180 top value=0.015uF (schematic designator C20)
C20_4 "GRM155R71C153KA01D" 0402 5387.64,4720 r180 top value=0.015uF (schematic designator C20)
C21_1 "GRM21BR61H475KE51L" 0805_HV 780,2661.42 r180 top value=4.7uF (schematic designator C21)
C21_2 "GRM21BR61H475KE51L" 0805_HV 2200.12,2665 r180 top value=4.7uF (schematic designator C21)
C21_3 "GRM21BR61H475KE51L" 0805_HV 3675.12,2665 r180 top value=4.7uF (schematic designator C21)
C21_4 "GRM21BR61H475KE51L" 0805_HV 5120.9,2658.16 r180 top value=4.7uF (schematic designator C21)
C22_1 "GRM155R61C104KA88D" 0402 803.62,2721.42 r0 top value=0.1uF (schematic designator C22)
C22_2 "GRM155R61C104KA88D" 0402 2223.74,2725 r0 top value=0.1uF (schematic designator C22)
C22_3 "GRM155R61C104KA88D" 0402 3698.74,2725 r0 top value=0.1uF (schematic designator C22)
C22_4 "GRM155R61C104KA88D" 0402 5144.52,2718.16 r0 top value=0.1uF (schematic designator C22)
C23_1 "GRM155R61C104KA88D" 0402 1494.34,5085.9 r180 top value=0.1uF (schematic designator C23)
C23_2 "GRM155R61C104KA88D" 0402 2920.77,5089.65 r180 top value=0.1uF (schematic designator C23)
C23_3 "GRM155R61C104KA88D" 0402 4395.77,5089.65 r180 top value=0.1uF (schematic designator C23)
C23_4 "GRM155R61C104KA88D" 0402 5841.55,5082.81 r180 top value=0.1uF (schematic designator C23)
C24_1 "GRM188R71H224KAC4D" 0603 823.62,2921.42 r180 top value=0.22uF (schematic designator C24)
C24_2 "GRM188R71H224KAC4D" 0603 2243.74,2925 r180 top value=0.22uF (schematic designator C24)
C24_3 "GRM188R71H224KAC4D" 0603 3718.74,2925 r180 top value=0.22uF (schematic designator C24)
C24_4 "GRM188R71H224KAC4D" 0603 5164.52,2918.16 r180 top value=0.22uF (schematic designator C24)
C25_1 "GRM155R61C104KA88D" 0402 1350.85,4917.76 r0 top value=0.1uF (schematic designator C25)
C25_2 "GRM155R61C104KA88D" 0402 2770.97,4921.34 r0 top value=0.1uF (schematic designator C25)
C25_3 "GRM155R61C104KA88D" 0402 4245.97,4921.34 r0 top value=0.1uF (schematic designator C25)
C25_4 "GRM155R61C104KA88D" 0402 5691.75,4914.5 r0 top value=0.1uF (schematic designator C25)
C26_1 "GRM155R61C104KA88D" 0402 683.62,2867.48 r0 bottom value=0.1uF (schematic designator C26)
C26_2 "GRM155R61C104KA88D" 0402 2103.74,2871.06 r0 bottom value=0.1uF (schematic designator C26)
C26_3 "GRM155R61C104KA88D" 0402 3578.74,2871.06 r0 bottom value=0.1uF (schematic designator C26)
C26_4 "GRM155R61C104KA88D" 0402 5024.52,2864.22 r0 bottom value=0.1uF (schematic designator C26)
C27_1 "GRM155R61C104KA88D" 0402 513.62,2741.42 r0 top value=0.1uF (schematic designator C27)
C27_2 "GRM155R61C104KA88D" 0402 1933.74,2745 r0 top value=0.1uF (schematic designator C27)
C27_3 "GRM155R61C104KA88D" 0402 3408.74,2745 r0 top value=0.1uF (schematic designator C27)
C27_4 "GRM155R61C104KA88D" 0402 4854.52,2738.16 r0 top value=0.1uF (schematic designator C27)
C28_1 "GRM1555C1H102JA01D" 0402 6184.41,1481.6 r270 top value=1000pF (schematic designator C28)
C28_2 "GRM1555C1H102JA01D" 0402 5995,1465 r270 top value=1000pF (schematic designator C28)
C28_3 "GRM1555C1H102JA01D" 0402 5770,1465 r270 top value=1000pF (schematic designator C28)
C28_4 "GRM1555C1H102JA01D" 0402 5543.42,1483.16 r270 top value=1000pF (schematic designator C28)
C29_1 "GRM155R61C104KA88D" 0402 6052.82,1268.12 r90 bottom value=0.1uF (schematic designator C29)
C29_2 "GRM155R61C104KA88D" 0402 5843.78,1258.15 r90 bottom value=0.1uF (schematic designator C29)
C29_3 "GRM155R61C104KA88D" 0402 5634.87,1252.03 r90 bottom value=0.1uF (schematic designator C29)
C29_4 "GRM155R61C104KA88D" 0402 5413.78,1272.02 r90 bottom value=0.1uF (schematic designator C29)
C30_1 "GRM155R61C104KA88D" 0402 6035.64,1790.13 r0 bottom value=0.1uF (schematic designator C30)
C30_2 "GRM155R61C104KA88D" 0402 5755,1800 r0 bottom value=0.1uF (schematic designator C30)
C30_3 "GRM155R61C104KA88D" 0402 5470.29,1801.45 r0 bottom value=0.1uF (schematic designator C30)
C30_4 "GRM155R61C104KA88D" 0402 5208.49,1806.39 r0 bottom value=0.1uF (schematic designator C30)
C31_1 "GRM1885C1H332JA01D" 0603 6132.82,1408.12 r180 top value=3300pF (schematic designator C31)
C31_2 "GRM1885C1H332JA01D" 0603 5924.79,1394.32 r180 top value=3300pF (schematic designator C31)
C31_3 "GRM1885C1H332JA01D" 0603 5714.87,1392.03 r180 top value=3300pF (schematic designator C31)
C31_4 "GRM1885C1H332JA01D" 0603 5493.78,1412.02 r180 top value=3300pF (schematic designator C31)
C32_1 "GRM1555C1H102JA01D" 0402 6079.41,1481.6 r270 top value=1000pF (schematic designator C32)
C32_2 "GRM1555C1H102JA01D" 0402 5874.48,1465.69 r270 top value=1000pF (schematic designator C32)
C32_3 "GRM1555C1H102JA01D" 0402 5649.56,1469.2 r270 top value=1000pF (schematic designator C32)
C32_4 "GRM1555C1H102JA01D" 0402 5443.42,1483.16 r270 top value=1000pF (schematic designator C32)
C33_1 "GRM155R61C104KA88D" 0402 6222.82,1328.12 r270 bottom value=0.1uF (schematic designator C33)
C33_2 "GRM155R61C104KA88D" 0402 6014.79,1314.32 r270 bottom value=0.1uF (schematic designator C33)
C33_3 "GRM155R61C104KA88D" 0402 5804.87,1312.03 r270 bottom value=0.1uF (schematic designator C33)
C33_4 "GRM155R61C104KA88D" 0402 5583.78,1332.02 r270 bottom value=0.1uF (schematic designator C33)
C34_1 "GRM155R61C104KA88D" 0402 6192.87,1695.56 r270 top value=0.1uF (schematic designator C34)
C34_2 "GRM155R61C104KA88D" 0402 5905.98,1698.81 r270 top value=0.1uF (schematic designator C34)
C34_3 "GRM155R61C104KA88D" 0402 5623.54,1690.07 r270 top value=0.1uF (schematic designator C34)
C34_4 "GRM155R61C104KA88D" 0402 5359.01,1694.66 r270 top value=0.1uF (schematic designator C34)
C35_1 "GRM155R61E472KA01D" 0402 3858.78,964.64 r270 top value=4700pF (schematic designator C35)
C35_2 "GRM155R61E472KA01D" 0402 3577.24,964.2 r270 top value=4700pF (schematic designator C35)
C35_3 "GRM155R61E472KA01D" 0402 3290.29,969.4 r270 top value=4700pF (schematic designator C35)
C35_4 "GRM155R61E472KA01D" 0402 2991.87,966.38 r270 top value=4700pF (schematic designator C35)
C36_1 "GRM155R61C104KA88D" 0402 6083.32,1723.58 r180 top value=0.1uF (schematic designator C36)
C36_2 "GRM155R61C104KA88D" 0402 5806.3,1725.57 r180 top value=0.1uF (schematic designator C36)
C36_3 "GRM155R61C104KA88D" 0402 5523.11,1718.45 r180 top value=0.1uF (schematic designator C36)
C36_4 "GRM155R61C104KA88D" 0402 5258.25,1724.83 r180 top value=0.1uF (schematic designator C36)
C37_1 "GRM188R72A332KA01D" 0603 3822.5,1335.12 r90 top value=3300pF (schematic designator C37)
C37_2 "GRM188R72A332KA01D" 0603 3535.15,1333.57 r90 top value=3300pF (schematic designator C37)
C37_3 "GRM188R72A332KA01D" 0603 3248.72,1336.34 r90 top value=3300pF (schematic designator C37)
C37_4 "GRM188R72A332KA01D" 0603 2944.39,1337.58 r90 top value=3300pF (schematic designator C37)
C38_1 "GRM155R61C104KA88D" 0402 3990.3,1082.37 r270 top value=0.1uF (schematic designator C38)
C38_2 "GRM155R61C104KA88D" 0402 3712.46,1070.04 r270 top value=0.1uF (schematic designator C38)
C38_3 "GRM155R61C104KA88D" 0402 3421.51,1088.58 r270 top value=0.1uF (schematic designator C38)
C38_4 "GRM155R61C104KA88D" 0402 3117.19,1085.39 r270 top value=0.1uF (schematic designator C38)
C39_1 "GRM155R61C104KA88D" 0402 3820.3,1217.37 r90 top value=0.1uF (schematic designator C39)
C39_2 "GRM155R61C104KA88D" 0402 3544.88,1209.81 r90 top value=0.1uF (schematic designator C39)
C39_3 "GRM155R61C104KA88D" 0402 3251.51,1223.58 r90 top value=0.1uF (schematic designator C39)
C39_4 "GRM155R61C104KA88D" 0402 2947.19,1220.39 r90 top value=0.1uF (schematic designator C39)
C40 "GRM188R72A104KA35D" 0603 812.22,327.48 r180 top value=0.1uF
C41 "GMK325BJ226MM-P" 1210 1210,315.76 r0 top value=22uF
C42 "GMK325BJ226MM-P" 1210 1160,480 r90 top value=22uF
C43 "GMK325BJ226MM-P" 1210 1015,140 r270 top value=22uF
C44 "GRM188R72A104KA35D" 0603 920,172.51 r270 top value=0.1uF
C45 "GRM155R61C104KA88D" 0402 1675,711.08 r270 top value=0.1uF
C46 "CGA3E1X7R1E105K080AC" 0603S 1863.82,1077.37 r0 top value=1uF
C47 "CGA3E1X7R1E105K080AC" 0603S 2003.82,1077.37 r180 top value=1uF
C48 "GMK325BJ226MM-P" 1210 1595,738.14 r90 top value=22uF
C49 "F381A225MMA" 0603S 2070.69,835.56 r90 top value=2.2uF
C50 "CGA3E1X7R1E105K080AC" 0603S 2215.39,819.22 r0 top value=1uF
C51 "CGA3E1X7R1E105K080AC" 0603S 2445.39,729.22 r270 top value=1uF
C52 "CGA3E1X7R1E105K080AC" 0603S 1721.06,708.14 r90 top value=1uF
C53 "GRM155R61C104KA88D" 0402 1885.32,957.37 r270 top value=0.1uF
C54 "GRM155R61C104KA88D" 0402 2246.89,699.22 r270 top value=0.1uF
C55 "GRM188R61E106MA73D" 0603 2650,1020 r0 top value=10uF
C56 "GRM155R61C104KA88D" 0402 2640,975 r180 top value=0.1uF
C57 "GRM21BR71H105KA12L" 0805_HV 2905,446.5 r180 top value=1uF
C58 "F381A225MMA" 0603S 2474.56,1115.48 r90 top value=1uF
C59 "GMK325BJ226MM-P" 1210 2650,712.91 r270 top value=22uF
C60 "CGA3E1X7R1E105K080AC" 0603S 2149.89,960.96 r180 top value=1uF
C61 "GRM155R71C153KA01D" 0402 2570,851.42 r90 top value=0.015uF
C62 "GRM21BR71H105KA12L" 0805_HV 3072.4,507.27 r270 top value=1uF
C63 "GRM21BR71H105KA12L" 0805_HV 2736.44,550.94 r180 top value=1uF
C64 "GRM155R61C104KA88D" 0402S 5036.62,940.88 r90 bottom value=0.1uF
C65 "GRM155R61C104KA88D" 0402S 5035,935 r90 top value=0.1uF
C66 "CGA3E1X7R1E105K080AC" 0603S 4634.91,946.36 r90 top value=1uF
C67 "GRM188R61E106MA73D" 0603 4608.14,1059.5 r90 bottom value=10uF
C68 "CGA3E1X7R1E105K080AC" 0603S 5086.02,1048.73 r90 top value=1uF
C69 "GRM155R61C104KA88D" 0402S 5045.06,1048.19 r90 bottom value=0.1uF
C70 "GRM155R61C104KA88D" 0402S 4649.11,1050.57 r270 bottom value=0.1uF
C71 "GRM155R61C104KA88D" 0402S 5046.94,1051.35 r90 top value=0.1uF
C72 "GRM155R61C104KA88D" 0402S 4646.25,1046.5 r270 top value=0.1uF
C73 "CGA3E1X7R1E105K080AC" 0603S 4985.49,870 r180 bottom value=1uF
C74 "CGA3E1X7R1E105K080AC" 0603S 4985,870 r180 top value=1uF
C75 "GRM155R61C104KA88D" 0402S 4690.17,872.39 r0 bottom value=0.1uF
C76 "GRM155R61C104KA88D" 0402S 4683.37,868.41 r0 top value=0.1uF
C77 "GRM188R61E106MA73D" 0603 5251.42,1080.23 r180 top value=10uF
C78 "GRM188Z71C475KE21D" 0603 5077.86,944.21 r270 top value=4.7uF
C79 "GRM188Z71C475KE21D" 0603 4606.85,1055.4 r90 top value=4.7uF
C80 "GRM188R61E106MA73D" 0603 4397.66,1034.55 r180 top value=10uF
C81 "GRM188R61E106MA73D" 0603 4884.35,644.36 r270 top value=10uF
C82 "CGA3E1X7R1E105K080AC" 0603S 3702.22,724.72 r270 top value=1uF
C83 "GRM155R61C104KA88D" 0402S 3740,725 r90 top value=0.1uF
C84 "GRM155R61C104KA88D" 0402S 3930.65,765.37 r90 top value=0.1uF
C85 "CGA3E1X7R1E105K080AC" 0603S 3971.43,734.48 r90 top value=1uF
C86 "CGA3E1X7R1E105K080AC" 0603S 5798.64,890.5 r90 top value=1uF
C87 "CGA3E1X7R1E105K080AC" 0603S 5488.64,995.5 r180 top value=1uF
C88 "GRM155R71C104JA88D" 0402 4140,1073.86 r270 top value=0.1uF
C89 "GRM155R61C104KA88D" 0402S 4174.23,676.84 r270 top value=0.1uF
C90 "GRM188R61E106MA73D" 0603 5423.64,945.5 r0 top value=10uF
C91 "GRM155R71C104JA88D" 0402 4206.6,669.4 r270 top value=0.1uF
C92 "GRM155R61C104KA88D" 0402 3130,2940.71 r90 top value=0.1uF
C93 "GCM155R71C224KE02D" 0402 3130,2806.69 r90 top value=0.22uF
C94 "GRM155R71C103KA01D" 0402 5441,485.5 r90 top value=0.01uF
C95 "GRM155R71C103KA01D" 0402 5202.07,485.5 r270 top value=0.01uF
C96 "GRM155R71C103KA01D" 0402 5135.07,485.5 r270 top value=0.01uF
C97 "GRM155R71C103KA01D" 0402 5070.07,485.5 r270 top value=0.01uF
C98 "GRM155R71C103KA01D" 0402 5038.07,485.5 r270 top value=0.01uF
C99 "GRM155R61C104KA88D" 0402 3707,52.5 r0 top value=0.1uF
C100 "GRM155R61C104KA88D" 0402 2124.5,470 r0 top value=0.1uF
C101 "GRM155R61C104KA88D" 0402 3736,485.5 r90 top value=0.1uF
C102 "GRM155R71C153KA01D" 0402 2461.5,482.18 r0 top value=0.015uF
C103 "GRM155R61C104KA88D" 0402 3985.69,52.5 r180 top value=0.1uF
C104 "GRM155R61C104KA88D" 0402 4888,53.5 r180 top value=0.1uF
C105 "GRM155R61C104KA88D" 0402 2168.51,822.27 r0 bottom value=0.1uF
C106 "GRM155R61C104KA88D" 0402 2168.51,279.27 r0 bottom value=0.1uF
C107_1 "GRM155R61C104KA88D" 0402 980.47,4551.06 r90 top value=0.1uF (schematic designator C107)
C107_2 "GRM155R61C104KA88D" 0402 2400.59,4554.65 r90 top value=0.1uF (schematic designator C107)
C107_3 "GRM155R61C104KA88D" 0402 3875.59,4554.65 r90 top value=0.1uF (schematic designator C107)
C107_4 "GRM155R61C104KA88D" 0402 5321.37,4547.81 r90 top value=0.1uF (schematic designator C107)
C108_1 "GRM155R71C104JA88D" 0402 1225.9,3684.08 r180 top value=0.1uF (schematic designator C108)
C108_2 "GRM155R71C104JA88D" 0402 2646.01,3687.67 r180 top value=0.1uF (schematic designator C108)
C108_3 "GRM155R71C104JA88D" 0402 4121.01,3687.67 r180 top value=0.1uF (schematic designator C108)
C108_4 "GRM155R71C104JA88D" 0402 5566.79,3680.83 r180 top value=0.1uF (schematic designator C108)
D1 "150060VS75000" WL-SMCW_GREEN 1963.82,897.37 r180 top value=Green
D2 "150060VS75000" WL-SMCW_GREEN 2345.39,817.01 r0 top value=Green
D3 "150060VS75000" WL-SMCW_GREEN 2740,681.42 r90 top value=Green
D4 "150060VS75000" WL-SMCW_GREEN 3954.19,572 r0 top value=Green
F1_1 "CB61F15A-TR1" 6125FA 685.97,2244.08 r270 top (schematic designator F1)
F1_2 "CB61F15A-TR1" 6125FA 2106.09,2247.67 r270 top (schematic designator F1)
F1_3 "CB61F15A-TR1" 6125FA 3581.09,2247.67 r270 top (schematic designator F1)
F1_4 "CB61F15A-TR1" 6125FA 4917.42,2240.26 r270 top (schematic designator F1)
FID1 "Fiducial" Fiducial10-20 6000,400 r0 top
FID2 "Fiducial" Fiducial10-20 400,400 r0 top
FID3 "Fiducial" Fiducial10-20 146.05,5680 r0 top
H1 "NY PMS 440 0025 PH" "NY PMS 440 0025 PH" 6200,200 r0 top locked
H2 "NY PMS 440 0025 PH" "NY PMS 440 0025 PH" 200,200 r0 top locked
H3 "NY PMS 440 0025 PH" "NY PMS 440 0025 PH" 200,6000 r0 top locked
H4 "NY PMS 440 0025 PH" "NY PMS 440 0025 PH" 6200,6000 r0 top locked
H5 "1902C" Keystone_1902C 6200,200 r180 bottom locked
H6 "1902C" Keystone_1902C 200,200 r180 bottom locked
H7 "1902C" Keystone_1902C 200,6000 r180 bottom locked
H8 "1902C" Keystone_1902C 6200,6000 r180 bottom locked
J1 "108-0740-001" Johnson_108-0740-001 500.19,1550 r0 top
J2 "108-0740-001" Johnson_108-0740-001 504.28,890 r0 top
J3 "B2B-EH-A(LF)(SN)" JST_B2B-EH-A 6293.25,1065.95 r270 top
J4 "B2B-EH-A(LF)(SN)" JST_B2B-EH-A 6189.56,749 r270 top
J5 "HTSW-103-07-G-S" Samtec_HTSW-103-07-G-S 6310,756.23 r90 top
J6 "HTSW-103-07-G-S" Samtec_HTSW-103-07-G-S 6310,4015 r90 top
J7_1 "CXS35-36T-C" FP-CXS35-36T-C_TERMINAL_LUG-MFG 632.02,6185 r270 top (schematic designator J7)
J7_2 "CXS35-36T-C" FP-CXS35-36T-C_TERMINAL_LUG-MFG 2058.58,6198.8 r270 top (schematic designator J7)
J7_3 "CXS35-36T-C" FP-CXS35-36T-C_TERMINAL_LUG-MFG 3527.14,6195.07 r270 top (schematic designator J7)
J7_4 "CXS35-36T-C" FP-CXS35-36T-C_TERMINAL_LUG-MFG 4985,6190 r270 top (schematic designator J7)
J8_1 "B2B-EH-A(LF)(SN)" JST_B2B-EH-A 998.73,5579.08 r0 top (schematic designator J8)
J8_2 "B2B-EH-A(LF)(SN)" JST_B2B-EH-A 2418.85,5582.67 r0 top (schematic designator J8)
J8_3 "B2B-EH-A(LF)(SN)" JST_B2B-EH-A 3919.64,5572.67 r0 top (schematic designator J8)
J8_4 "B2B-EH-A(LF)(SN)" JST_B2B-EH-A 5339.63,5575.83 r0 top (schematic designator J8)
J9_1 "CXS35-36T-C" FP-CXS35-36T-C_TERMINAL_LUG-MFG 1417.76,6196.22 r270 top (schematic designator J9)
J9_2 "CXS35-36T-C" FP-CXS35-36T-C_TERMINAL_LUG-MFG 2784.74,6195.07 r270 top (schematic designator J9)
J9_3 "CXS35-36T-C" FP-CXS35-36T-C_TERMINAL_LUG-MFG 4345,6205 r270 top (schematic designator J9)
J9_4 "CXS35-36T-C" FP-CXS35-36T-C_TERMINAL_LUG-MFG 5758.65,6192.96 r270 top (schematic designator J9)
J10 "HTSW-102-07-G-S" Samtec_HTSW-102-07-G-S 1360,485 r90 top
J11 "HTSW-103-07-G-S" Samtec_HTSW-103-07-G-S 590,200 r90 top
J12 "HTSW-102-07-G-S" Samtec_HTSW-102-07-G-S 2905.18,689.38 r180 top
J13 "HSEC8-160-01-L-DV-A-BL" controlCARD-120HSEC 4672.42,243.3 r180 top
J14 "HSEC8-130-01-L-DV-A" controlCARD-180HSEC-60pinAddon 2324.42,241.56 r180 top
J15 "B2B-EH-A(LF)(SN)" JST_B2B-EH-A 1993.51,1224.38 r180 bottom
J16 "B2B-EH-A(LF)(SN)" JST_B2B-EH-A 2432.49,1228.85 r180 bottom
L1_1 "XAL1010-472MEB" XAL1010 912.24,3611.42 r90 top value=4.7uH (schematic designator L1)
L1_2 "XAL1010-472MEB" XAL1010 2332.36,3615 r90 top value=4.7uH (schematic designator L1)
L1_3 "XAL1010-472MEB" XAL1010 3807.36,3615 r90 top value=4.7uH (schematic designator L1)
L1_4 "XAL1010-472MEB" XAL1010 5253.14,3608.16 r90 top value=4.7uH (schematic designator L1)
L2 "LPS5015-183MLB" LPS5015 996.8,370.37 r0 top value=18uH
L3 "BLM41PG102SN1L" 1806_HighSpeed 1484.97,598.93 r90 top value="1000 ohm"
LBL1 "THT-14-423-10" Label_650x200 6059.75,4071.5 r90 bottom
Logo1 "CE Mark" CE_Mark_5mm 6033.95,2385 r270 bottom
Logo2 "Texas Instruments" TI_Stacked_Overlay_Small 6050,3250 r270 bottom
Logo3 "FCC disclaimer" FCC_disclaimer 11240,5310 r90 top
Logo4 "WEEE logo" WEEE_Minimum 6087.41,2679.81 r270 bottom
Logo5 "CAUTION HOT SURFACE" IEC_HotSurface_Large 3799.06,3575 r180 bottom
Logo6 "CAUTION HOT SURFACE" IEC_HotSurface_Large 5225,3610 r180 bottom
Q1_1 "CSD17501Q5A" DQJ0008A 1022.28,3054.33 r0 top value=30V (schematic designator Q1)
Q1_2 "CSD17501Q5A" DQJ0008A 2442.4,3057.91 r0 top value=30V (schematic designator Q1)
Q1_3 "CSD17501Q5A" DQJ0008A 3917.4,3057.91 r0 top value=30V (schematic designator Q1)
Q1_4 "CSD17501Q5A" DQJ0008A 5363.18,3051.07 r0 top value=30V (schematic designator Q1)
Q2_1 "CSD17573Q5B" DNK0008A 662.13,5040.67 r270 top value=30V (schematic designator Q2)
Q2_2 "CSD17573Q5B" DNK0008A 2082.24,5044.25 r270 top value=30V (schematic designator Q2)
Q2_3 "CSD17573Q5B" DNK0008A 3557.24,5044.25 r270 top value=30V (schematic designator Q2)
Q2_4 "CSD17573Q5B" DNK0008A 5003.02,5037.41 r270 top value=30V (schematic designator Q2)
Q3_1 "CSD17573Q5B" DNK0008A 663.46,5306.42 r90 top value=30V (schematic designator Q3)
Q3_2 "CSD17573Q5B" DNK0008A 2083.58,5310 r90 top value=30V (schematic designator Q3)
Q3_3 "CSD17573Q5B" DNK0008A 3558.58,5310 r90 top value=30V (schematic designator Q3)
Q3_4 "CSD17573Q5B" DNK0008A 5004.36,5303.16 r90 top value=30V (schematic designator Q3)
Q4_1 "CSD17501Q5A" DQJ0008A 748.46,3058.86 r0 top value=30V (schematic designator Q4)
Q4_2 "CSD17501Q5A" DQJ0008A 2168.58,3062.44 r0 top value=30V (schematic designator Q4)
Q4_3 "CSD17501Q5A" DQJ0008A 3643.58,3062.44 r0 top value=30V (schematic designator Q4)
Q4_4 "CSD17501Q5A" DQJ0008A 5089.36,3055.6 r0 top value=30V (schematic designator Q4)
Q5_1 "ISOM8110DFH" DFH0004A-MFG 1397.23,5167.76 r180 top value=80V (schematic designator Q5)
Q5_2 "ISOM8110DFH" DFH0004A-MFG 2817.35,5171.34 r180 top value=80V (schematic designator Q5)
Q5_3 "ISOM8110DFH" DFH0004A-MFG 4292.35,5171.34 r180 top value=80V (schematic designator Q5)
Q5_4 "ISOM8110DFH" DFH0004A-MFG 5738.13,5164.5 r180 top value=80V (schematic designator Q5)
Q6_1 "2N7002Q-7-F" SOT-23 1740.85,5027.76 r0 top value=60V (schematic designator Q6)
Q6_2 "2N7002Q-7-F" SOT-23 3160.97,5031.34 r0 top value=60V (schematic designator Q6)
Q6_3 "2N7002Q-7-F" SOT-23 4635.97,5031.34 r0 top value=60V (schematic designator Q6)
Q6_4 "2N7002Q-7-F" SOT-23 6081.75,5024.5 r0 top value=60V (schematic designator Q6)
Q7_1 "ISOM8110DFH" DFH0004A-MFG 1395.85,5287.76 r180 top value=80V (schematic designator Q7)
Q7_2 "ISOM8110DFH" DFH0004A-MFG 2815.97,5291.34 r180 top value=80V (schematic designator Q7)
Q7_3 "ISOM8110DFH" DFH0004A-MFG 4290.97,5291.34 r180 top value=80V (schematic designator Q7)
Q7_4 "ISOM8110DFH" DFH0004A-MFG 5736.75,5284.5 r180 top value=80V (schematic designator Q7)
Q8_1 "BSS84LT1G" FP-BSS84LT1G_SOT-23-3-318-08-MFG 1080.1,5060.35 r180 top (schematic designator Q8)
Q8_2 "BSS84LT1G" FP-BSS84LT1G_SOT-23-3-318-08-MFG 2500.22,5063.94 r180 top (schematic designator Q8)
Q8_3 "BSS84LT1G" FP-BSS84LT1G_SOT-23-3-318-08-MFG 3975.22,5063.94 r180 top (schematic designator Q8)
Q8_4 "BSS84LT1G" FP-BSS84LT1G_SOT-23-3-318-08-MFG 5421,5057.1 r180 top (schematic designator Q8)
R1_1 "SEWF3920F2L00P9" FP-SEWF3920F2L00P9_3920-MFG 662.13,4649.08 r90 top value=2m (schematic designator R1)
R1_2 "SEWF3920F2L00P9" FP-SEWF3920F2L00P9_3920-MFG 2094.36,4630 r90 top value=2m (schematic designator R1)
R1_3 "SEWF3920F2L00P9" FP-SEWF3920F2L00P9_3920-MFG 3575,4620 r90 top value=2m (schematic designator R1)
R1_4 "SEWF3920F2L00P9" FP-SEWF3920F2L00P9_3920-MFG 5015.14,4650 r90 top value=2m (schematic designator R1)
R2_1 "CRCW060349K9FKEA" 0603 874.37,2979.33 r180 bottom value=49.9k (schematic designator R2)
R2_2 "CRCW060349K9FKEA" 0603 2294.49,2982.91 r180 bottom value=49.9k (schematic designator R2)
R2_3 "CRCW060349K9FKEA" 0603 3769.49,2982.91 r180 bottom value=49.9k (schematic designator R2)
R2_4 "CRCW060349K9FKEA" 0603 5215.27,2976.07 r180 bottom value=49.9k (schematic designator R2)
R3_1 "CRCW080510R0JNEA" 0805_HV 1163.62,3221.42 r180 top value=10 (schematic designator R3)
R3_2 "CRCW080510R0JNEA" 0805_HV 2583.74,3225 r180 top value=10 (schematic designator R3)
R3_3 "CRCW080510R0JNEA" 0805_HV 4058.74,3225 r180 top value=10 (schematic designator R3)
R3_4 "CRCW080510R0JNEA" 0805_HV 5504.52,3218.16 r180 top value=10 (schematic designator R3)
R4_1 "CRCW06031R00FKEA" 0603 897.05,4524.68 r180 top value=1.00 (schematic designator R4)
R4_2 "CRCW06031R00FKEA" 0603 2317.17,4528.27 r180 top value=1.00 (schematic designator R4)
R4_3 "CRCW06031R00FKEA" 0603 3792.17,4528.27 r180 top value=1.00 (schematic designator R4)
R4_4 "CRCW06031R00FKEA" 0603 5237.94,4521.43 r180 top value=1.00 (schematic designator R4)
R5_1 "CRCW06031R00FKEA" 0603 897.05,4584.68 r180 top value=1.00 (schematic designator R5)
R5_2 "CRCW06031R00FKEA" 0603 2315,4590 r180 top value=1.00 (schematic designator R5)
R5_3 "CRCW06031R00FKEA" 0603 3792.17,4588.27 r180 top value=1.00 (schematic designator R5)
R5_4 "CRCW06031R00FKEA" 0603 5237.94,4581.43 r180 top value=1.00 (schematic designator R5)
R6_1 "CRCW04020000Z0ED" 0402 837.7,5444.08 r0 top value=0 (schematic designator R6)
R6_2 "CRCW04020000Z0ED" 0402 2257.81,5447.67 r0 top value=0 (schematic designator R6)
R6_3 "CRCW04020000Z0ED" 0402 3732.81,5447.67 r0 top value=0 (schematic designator R6)
R6_4 "CRCW04020000Z0ED" 0402 5178.59,5440.83 r0 top value=0 (schematic designator R6)
R7_1 "CRCW060349K9FKEA" 0603 650.24,3029.33 r270 bottom value=49.9k (schematic designator R7)
R7_2 "CRCW060349K9FKEA" 0603 2070.35,3032.91 r270 bottom value=49.9k (schematic designator R7)
R7_3 "CRCW060349K9FKEA" 0603 3545.35,3032.91 r270 bottom value=49.9k (schematic designator R7)
R7_4 "CRCW060349K9FKEA" 0603 4991.13,3026.07 r270 bottom value=49.9k (schematic designator R7)
R8_1 "CRCW04020000Z0ED" 0402 912.24,2911.42 r90 top value=0 (schematic designator R8)
R8_2 "CRCW04020000Z0ED" 0402 2332.36,2915 r90 top value=0 (schematic designator R8)
R8_3 "CRCW04020000Z0ED" 0402 3807.36,2915 r90 top value=0 (schematic designator R8)
R8_4 "CRCW04020000Z0ED" 0402 5253.14,2908.16 r90 top value=0 (schematic designator R8)
R9_1 "CRCW04020000Z0ED" 0402 1159.52,5444.08 r180 top value=0 (schematic designator R9)
R9_2 "CRCW04020000Z0ED" 0402 2579.64,5447.67 r180 top value=0 (schematic designator R9)
R9_3 "CRCW04020000Z0ED" 0402 4054.64,5447.67 r180 top value=0 (schematic designator R9)
R9_4 "CRCW04020000Z0ED" 0402 5500.42,5440.83 r180 top value=0 (schematic designator R9)
R10_1 "CRCW04020000Z0ED" 0402 660,2935.04 r180 top value=0 (schematic designator R10)
R10_2 "CRCW04020000Z0ED" 0402 2080.12,2938.62 r180 top value=0 (schematic designator R10)
R10_3 "CRCW04020000Z0ED" 0402 3555.12,2938.62 r180 top value=0 (schematic designator R10)
R10_4 "CRCW04020000Z0ED" 0402 5000.9,2931.78 r180 top value=0 (schematic designator R10)
R11_1 "CRCW04020000Z0ED" 0402 830,4625 r180 top value=0 (schematic designator R11)
R11_2 "CRCW04020000Z0ED" 0402 2255,4630 r180 top value=0 (schematic designator R11)
R11_3 "CRCW04020000Z0ED" 0402 3735,4630 r180 top value=0 (schematic designator R11)
R11_4 "CRCW04020000Z0ED" 0402 5195.61,4625.3 r180 top value=0 (schematic designator R11)
R12_1 "CRCW060310K0FKEA" 0603 1091.84,4654.47 r270 top value=10.0k (schematic designator R12)
R12_2 "CRCW060310K0FKEA" 0603 2505,4640 r270 top value=10.0k (schematic designator R12)
R12_3 "CRCW060310K0FKEA" 0603 3996.18,4656.65 r270 top value=10.0k (schematic designator R12)
R12_4 "CRCW060310K0FKEA" 0603 5413.01,4645 r270 top value=10.0k (schematic designator R12)
R13_1 "CRCW060310K0FKEA" 0603 1041.84,4657.3 r270 top value=10.0k (schematic designator R13)
R13_2 "CRCW060310K0FKEA" 0603 2455,4640 r270 top value=10.0k (schematic designator R13)
R13_3 "CRCW060310K0FKEA" 0603 3946.18,4656.65 r270 top value=10.0k (schematic designator R13)
R13_4 "CRCW060310K0FKEA" 0603 5363.01,4645 r270 top value=10.0k (schematic designator R13)
R14_1 "CRCW06031K00JNEA" 0603 1609.63,5142.76 r0 top value=1.0k (schematic designator R14)
R14_2 "CRCW06031K00JNEA" 0603 3029.75,5146.34 r0 top value=1.0k (schematic designator R14)
R14_3 "CRCW06031K00JNEA" 0603 4504.75,5146.34 r0 top value=1.0k (schematic designator R14)
R14_4 "CRCW06031K00JNEA" 0603 5950.53,5139.5 r0 top value=1.0k (schematic designator R14)
R15_1 "CRCW060310K0FKEA" 0603 1215.85,5082.76 r180 top value=10.0k (schematic designator R15)
R15_2 "CRCW060310K0FKEA" 0603 2635.97,5086.34 r180 top value=10.0k (schematic designator R15)
R15_3 "CRCW060310K0FKEA" 0603 4110.97,5086.34 r180 top value=10.0k (schematic designator R15)
R15_4 "CRCW060310K0FKEA" 0603 5556.75,5079.5 r180 top value=10.0k (schematic designator R15)
R16_1 "CRCW06034K99FKEAC" 0603 1215.85,4882.76 r180 top value=4.99k (schematic designator R16)
R16_2 "CRCW06034K99FKEAC" 0603 2635.97,4886.34 r180 top value=4.99k (schematic designator R16)
R16_3 "CRCW06034K99FKEAC" 0603 4110.97,4886.34 r180 top value=4.99k (schematic designator R16)
R16_4 "CRCW06034K99FKEAC" 0603 5556.75,4879.5 r180 top value=4.99k (schematic designator R16)
R17_1 "CRCW04020000Z0ED" 0402 870,2841.81 r270 top value=0 (schematic designator R17)
R17_2 "CRCW04020000Z0ED" 0402 2290,2845 r270 top value=0 (schematic designator R17)
R17_3 "CRCW04020000Z0ED" 0402 3765,2850 r270 top value=0 (schematic designator R17)
R17_4 "CRCW04020000Z0ED" 0402 5210,2840 r270 top value=0 (schematic designator R17)
R18_1 "CRCW06031K00JNEA" 0603 1174.47,5192.76 r0 top value=1.0k (schematic designator R18)
R18_2 "CRCW06031K00JNEA" 0603 2594.59,5196.34 r0 top value=1.0k (schematic designator R18)
R18_3 "CRCW06031K00JNEA" 0603 4069.59,5196.34 r0 top value=1.0k (schematic designator R18)
R18_4 "CRCW06031K00JNEA" 0603 5515.37,5189.5 r0 top value=1.0k (schematic designator R18)
R19_1 "CRCW060310K0FKEA" 0603 1215.85,5032.76 r0 top value=10.0k (schematic designator R19)
R19_2 "CRCW060310K0FKEA" 0603 2635.97,5036.34 r0 top value=10.0k (schematic designator R19)
R19_3 "CRCW060310K0FKEA" 0603 4110.97,5036.34 r0 top value=10.0k (schematic designator R19)
R19_4 "CRCW060310K0FKEA" 0603 5556.75,5029.5 r0 top value=10.0k (schematic designator R19)
R20_1 "CRCW060349K9FKEA" 0603 1215.85,4932.76 r180 top value=49.9k (schematic designator R20)
R20_2 "CRCW060349K9FKEA" 0603 2635.97,4936.34 r180 top value=49.9k (schematic designator R20)
R20_3 "CRCW060349K9FKEA" 0603 4110.97,4936.34 r180 top value=49.9k (schematic designator R20)
R20_4 "CRCW060349K9FKEA" 0603 5556.75,4929.5 r180 top value=49.9k (schematic designator R20)
R21_1 "CRCW060349K9FKEA" 0603 1036.3,5192.76 r180 top value=49.9k (schematic designator R21)
R21_2 "CRCW060349K9FKEA" 0603 2456.42,5196.34 r180 top value=49.9k (schematic designator R21)
R21_3 "CRCW060349K9FKEA" 0603 3931.42,5196.34 r180 top value=49.9k (schematic designator R21)
R21_4 "CRCW060349K9FKEA" 0603 5377.2,5189.5 r180 top value=49.9k (schematic designator R21)
R22_1 "CRCW06034K99FKEAC" 0603 1215.85,4982.76 r0 top value=4.99k (schematic designator R22)
R22_2 "CRCW06034K99FKEAC" 0603 2635.97,4986.34 r0 top value=4.99k (schematic designator R22)
R22_3 "CRCW06034K99FKEAC" 0603 4110.97,4986.34 r0 top value=4.99k (schematic designator R22)
R22_4 "CRCW06034K99FKEAC" 0603 5556.75,4979.5 r0 top value=4.99k (schematic designator R22)
R23_1 "CRCW060310K0FKEA" 0603 578.02,2789.08 r0 bottom value=10.0k (schematic designator R23)
R23_2 "CRCW060310K0FKEA" 0603 1998.14,2792.67 r0 bottom value=10.0k (schematic designator R23)
R23_3 "CRCW060310K0FKEA" 0603 3473.14,2792.67 r0 bottom value=10.0k (schematic designator R23)
R23_4 "CRCW060310K0FKEA" 0603 4918.92,2785.83 r0 bottom value=10.0k (schematic designator R23)
R24_1 "CRCW060310K0FKEA" 0603 580,2837.83 r0 bottom value=10.0k (schematic designator R24)
R24_2 "CRCW060310K0FKEA" 0603 2000.12,2841.42 r0 bottom value=10.0k (schematic designator R24)
R24_3 "CRCW060310K0FKEA" 0603 3475.12,2841.42 r0 bottom value=10.0k (schematic designator R24)
R24_4 "CRCW060310K0FKEA" 0603 4920.9,2834.58 r0 bottom value=10.0k (schematic designator R24)
R25_1 "CRCW060310K0FKEA" 0603 1610.85,5047.76 r180 top value=10.0k (schematic designator R25)
R25_2 "CRCW060310K0FKEA" 0603 3030.97,5051.34 r180 top value=10.0k (schematic designator R25)
R25_3 "CRCW060310K0FKEA" 0603 4505.97,5051.34 r180 top value=10.0k (schematic designator R25)
R25_4 "CRCW060310K0FKEA" 0603 5951.75,5044.5 r180 top value=10.0k (schematic designator R25)
R26_1 "CRCW06034K99FKEAC" 0603 1610.85,4897.76 r180 top value=4.99k (schematic designator R26)
R26_2 "CRCW06034K99FKEAC" 0603 3030.97,4901.34 r180 top value=4.99k (schematic designator R26)
R26_3 "CRCW06034K99FKEAC" 0603 4505.97,4901.34 r180 top value=4.99k (schematic designator R26)
R26_4 "CRCW06034K99FKEAC" 0603 5951.75,4894.5 r180 top value=4.99k (schematic designator R26)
